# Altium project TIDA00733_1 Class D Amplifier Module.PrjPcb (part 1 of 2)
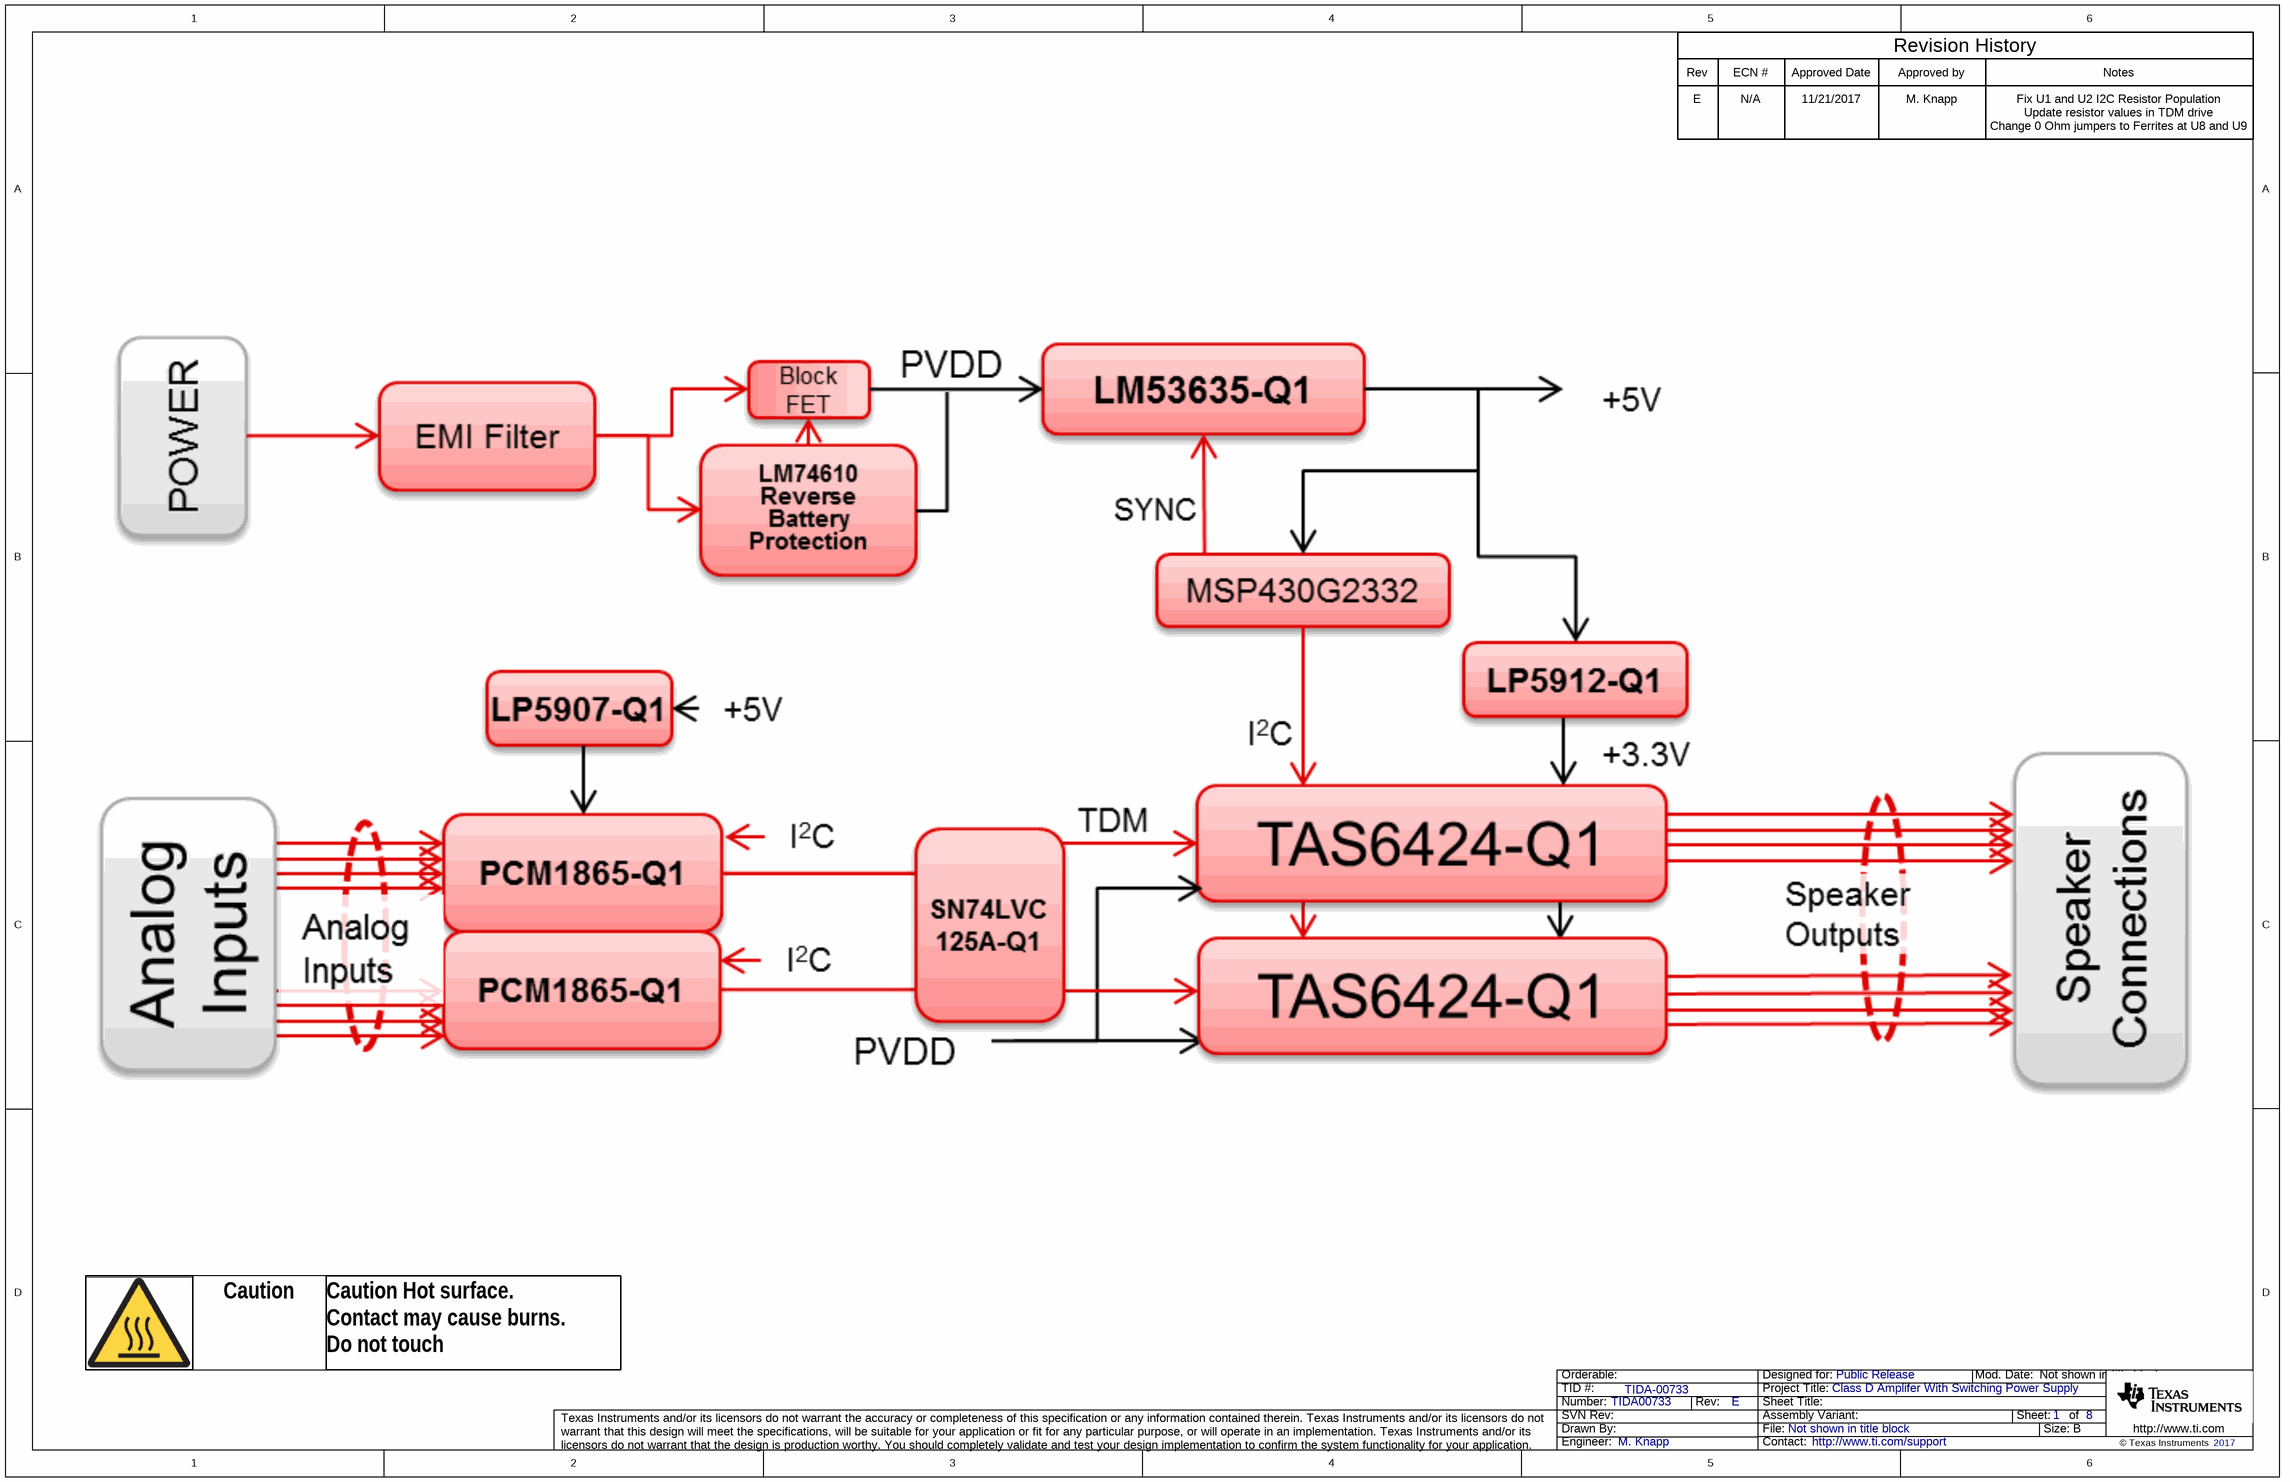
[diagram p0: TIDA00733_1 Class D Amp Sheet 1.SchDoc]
CopyrightYear: 2017; PCB_Layout: M. Knapp; PCB_Rev: E; PRJ_Customer: Public Release; PRJ_Engineer: M. Knapp; PRJ_Number: TIDA00733; PRJ_Title: Class D Amplifer With Switching Power Supply; SCH_Rev: E; TechSupport: http://www.ti.com/support; TID: TIDA-00733
8 sheets, 308 parts. Net scope: global (net labels, ports and power ports of the same name join across sheets).
Board file: TIDA00733_1 Class D Amp PCB.PcbDoc
Sheets:
  TIDA00733_1 Class D Amp Sheet 1.SchDoc
  TIDA00733_1 Class D Amp Sheet 2.SchDoc
  TIDA00733_1 Class D Amp Sheet 3.SchDoc
  TIDA00733_1 Class D Amp Sheet 4.SchDoc
  TIDA00733_1 Class D Amp Sheet 5.SchDoc
  TIDA00733_1 Class D Amp Sheet 6.SchDoc
  TIDA00733_1 Class D Amp Sheet 7.SchDoc
  TIDA00733_1 Class D Amp Sheet 8.SchDoc

## Sheet TIDA00733_1 Class D Amp Sheet 1.SchDoc
size 431 x 279 mm; Date: Not shown in title block; ApprovedBy: Not shown in title block; CheckedBy: Not shown in title block; Author: Not shown in title block; CompanyName: Not shown in title block; Engineer: Not shown in title block; Organization: Not shown in title block; Address1: Not shown in title block; Address2: Not shown in title block; Address3: Not shown in title block; Address4: Not shown in title block; DocumentNumber: 1; Revision: Use project parameter SCH_Rev; SheetNumber: 1; SheetTotal: 8; PageSetup: Record=PageOptions¦CenterHorizontal=True¦CenterVertical=True¦PrintScale=1.00¦XCorrection=1.00¦YCorrection=1.00¦PrintKind=0¦BorderSize=5000000¦LeftOffset=0¦BottomOffset=0¦Orientation=2¦PaperLength=1000¦PaperWidth=1000¦Scale=100¦PaperSource=15¦PrintQuality=600¦MediaType=1¦DitherType=10¦PaperKind=Letter¦PrintScaleMode=1

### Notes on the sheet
- Rev
- E
- ECN #
- N/A
- Approved Date
- 11/21/2017
- Approved by
- M. Knapp
- Revision History
- Notes
- Fix U1 and U2 I2C Resistor Population
- Update resistor values in TDM drive
- Change 0 Ohm jumpers to Ferrites at U8 and U9
- Caution
- Caution Hot surface.
  Contact may cause burns.
  Do not touch

## Sheet TIDA00733_1 Class D Amp Sheet 2.SchDoc
size 431 x 279 mm; Date: Not shown in title block; ApprovedBy: Not shown in title block; CheckedBy: Not shown in title block; Author: Not shown in title block; CompanyName: Not shown in title block; Engineer: Not shown in title block; Organization: Not shown in title block; Address1: Not shown in title block; Address2: Not shown in title block; Address3: Not shown in title block; Address4: Not shown in title block; DocumentNumber: 2; Revision: Use project parameter SCH_Rev; SheetNumber: 2; SheetTotal: 8; PageSetup: Record=PageOptions¦CenterHorizontal=True¦CenterVertical=True¦PrintScale=1.00¦XCorrection=1.00¦YCorrection=1.00¦PrintKind=0¦BorderSize=5000000¦LeftOffset=0¦BottomOffset=0¦Orientation=2¦PaperLength=1000¦PaperWidth=1000¦Scale=100¦PaperSource=15¦PrintQuality=600¦MediaType=1¦DitherType=10¦PaperKind=Letter¦PrintScaleMode=1
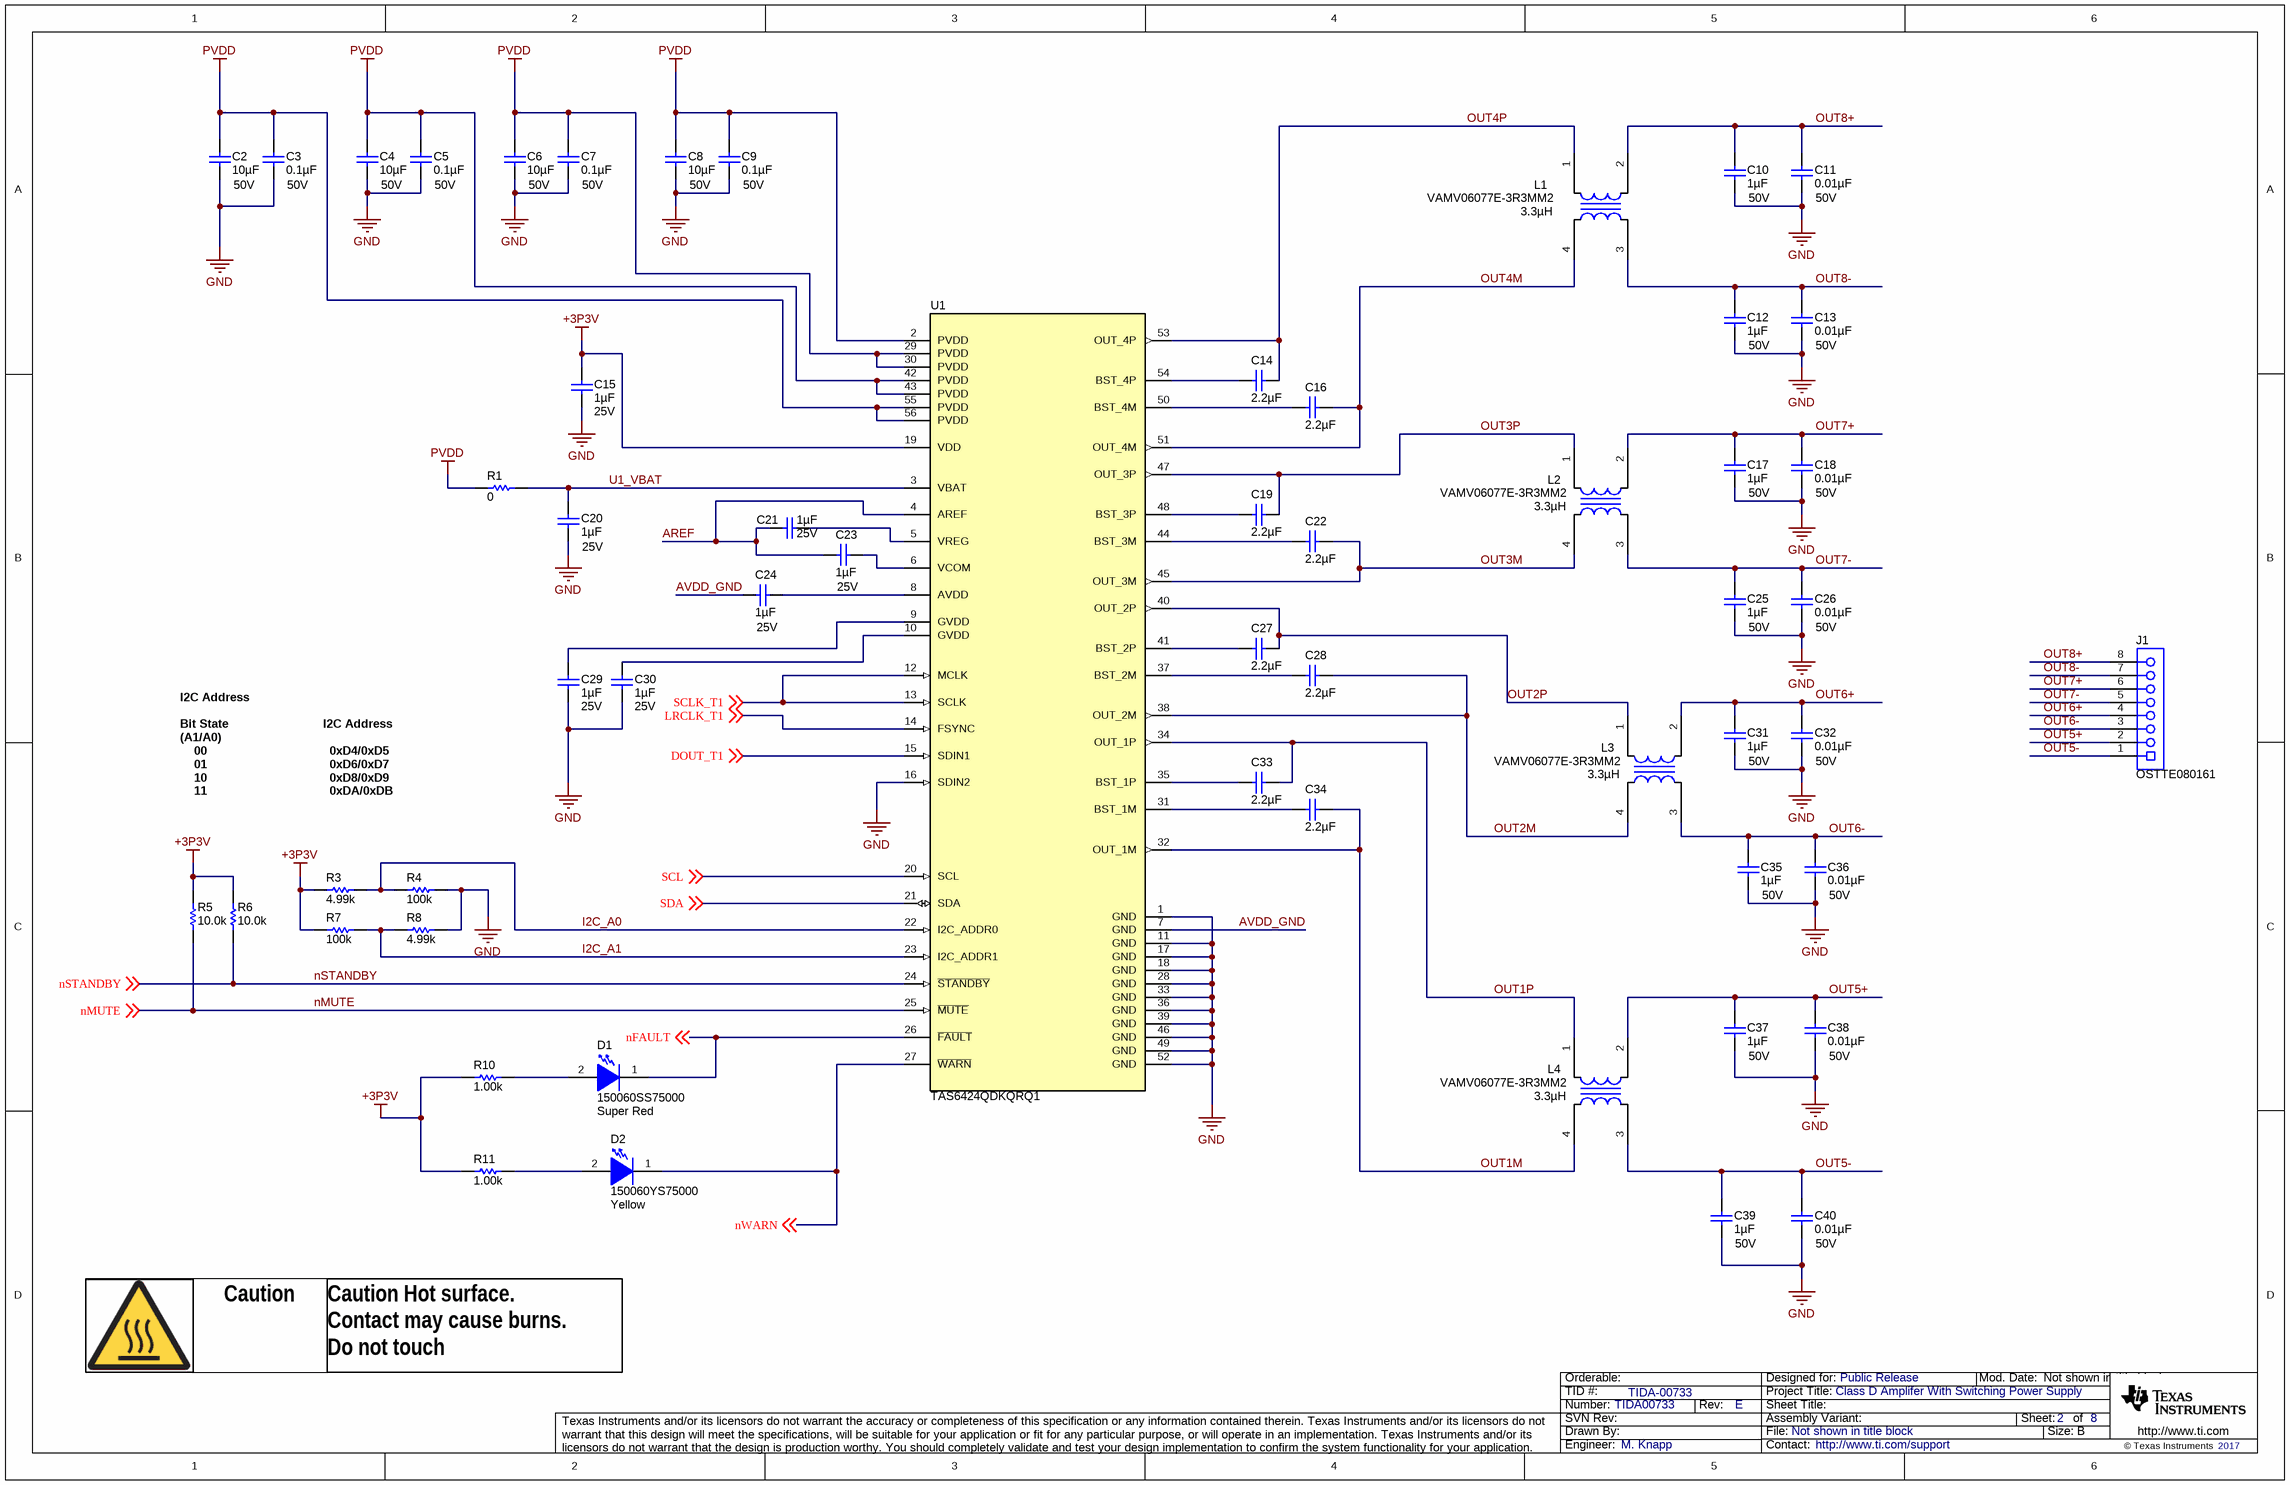
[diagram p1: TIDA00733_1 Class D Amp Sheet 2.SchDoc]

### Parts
C2  ValueDisplayed: 10µF  Value2: 50V  [1210_270]  (hidden comment: GRM32ER71H106KA12L)
C3  ValueDisplayed: 0.1µF  Value2: 50V  [0402L]  (hidden comment: C1005X7R1H104K050BB)
C4  ValueDisplayed: 10µF  Value2: 50V  [1210_270]  (hidden comment: GRM32ER71H106KA12L)
C5  ValueDisplayed: 0.1µF  Value2: 50V  [0402L]  (hidden comment: C1005X7R1H104K050BB)
C6  ValueDisplayed: 10µF  Value2: 50V  [1210_270]  (hidden comment: GRM32ER71H106KA12L)
C7  ValueDisplayed: 0.1µF  Value2: 50V  [0402L]  (hidden comment: C1005X7R1H104K050BB)
C8  ValueDisplayed: 10µF  Value2: 50V  [1210_270]  (hidden comment: GRM32ER71H106KA12L)
C9  ValueDisplayed: 0.1µF  Value2: 50V  [0402L]  (hidden comment: C1005X7R1H104K050BB)
C10  ValueDisplayed: 1µF  Value2: 50V  [0805L]  (hidden comment: GRM21BR71H105KA12L)
C11  ValueDisplayed: 0.01µF  Value2: 50V  [0402L]  (hidden comment: GCM155R71H103KA55D)
C12  ValueDisplayed: 1µF  Value2: 50V  [0805L]  (hidden comment: GRM21BR71H105KA12L)
C13  ValueDisplayed: 0.01µF  Value2: 50V  [0402L]  (hidden comment: GCM155R71H103KA55D)
C14  ValueDisplayed: 2.2µF  [0805L]  (hidden comment: C2012X7R1H225K125AC)
C15  ValueDisplayed: 1µF  Value2: 25V  [0603L]  (hidden comment: C1608X7R1E105K080AB)
C16  ValueDisplayed: 2.2µF  [0805L]  (hidden comment: C2012X7R1H225K125AC)
C17  ValueDisplayed: 1µF  Value2: 50V  [0805L]  (hidden comment: GRM21BR71H105KA12L)
C18  ValueDisplayed: 0.01µF  Value2: 50V  [0402L]  (hidden comment: GCM155R71H103KA55D)
C19  ValueDisplayed: 2.2µF  [0805L]  (hidden comment: C2012X7R1H225K125AC)
C20  ValueDisplayed: 1µF  Value2: 25V  [0603L]  (hidden comment: C1608X7R1E105K080AB)
C21  ValueDisplayed: 1µF  Value2: 25V  [0603L]  (hidden comment: C1608X7R1E105K080AB)
C22  ValueDisplayed: 2.2µF  [0805L]  (hidden comment: C2012X7R1H225K125AC)
C23  ValueDisplayed: 1µF  Value2: 25V  [0603L]  (hidden comment: C1608X7R1E105K080AB)
C24  ValueDisplayed: 1µF  Value2: 25V  [0603L]  (hidden comment: C1608X7R1E105K080AB)
C25  ValueDisplayed: 1µF  Value2: 50V  [0805L]  (hidden comment: GRM21BR71H105KA12L)
C26  ValueDisplayed: 0.01µF  Value2: 50V  [0402L]  (hidden comment: GCM155R71H103KA55D)
C27  ValueDisplayed: 2.2µF  [0805L]  (hidden comment: C2012X7R1H225K125AC)
C28  ValueDisplayed: 2.2µF  [0805L]  (hidden comment: C2012X7R1H225K125AC)
C29  ValueDisplayed: 1µF  Value2: 25V  [0603L]  (hidden comment: C1608X7R1E105K080AB)
C30  ValueDisplayed: 1µF  Value2: 25V  [0603L]  (hidden comment: C1608X7R1E105K080AB)
C31  ValueDisplayed: 1µF  Value2: 50V  [0805L]  (hidden comment: GRM21BR71H105KA12L)
C32  ValueDisplayed: 0.01µF  Value2: 50V  [0402L]  (hidden comment: GCM155R71H103KA55D)
C33  ValueDisplayed: 2.2µF  [0805L]  (hidden comment: C2012X7R1H225K125AC)
C34  ValueDisplayed: 2.2µF  [0805L]  (hidden comment: C2012X7R1H225K125AC)
C35  ValueDisplayed: 1µF  Value2: 50V  [0805L]  (hidden comment: GRM21BR71H105KA12L)
C36  ValueDisplayed: 0.01µF  Value2: 50V  [0402L]  (hidden comment: GCM155R71H103KA55D)
C37  ValueDisplayed: 1µF  Value2: 50V  [0805L]  (hidden comment: GRM21BR71H105KA12L)
C38  ValueDisplayed: 0.01µF  Value2: 50V  [0402L]  (hidden comment: GCM155R71H103KA55D)
C39  ValueDisplayed: 1µF  Value2: 50V  [0805L]  (hidden comment: GRM21BR71H105KA12L)
C40  ValueDisplayed: 0.01µF  Value2: 50V  [0402L]  (hidden comment: GCM155R71H103KA55D)
D1  value Super Red  [WL-SMCW_RED]  (hidden comment: 150060SS75000)
D2  value Yellow  [WL-SMCW_YELLOW]  (hidden comment: 150060YS75000)
J1  OSTTE080161  [On-Shore_OSTTE080161]
L1  VAMV06077E-3R3MM2  ValueDisplayed: 3.3µH  [Cyntec_VAMV06077E]
L2  VAMV06077E-3R3MM2  ValueDisplayed: 3.3µH  [Cyntec_VAMV06077E]
L3  VAMV06077E-3R3MM2  ValueDisplayed: 3.3µH  [Cyntec_VAMV06077E]
L4  VAMV06077E-3R3MM2  ValueDisplayed: 3.3µH  [Cyntec_VAMV06077E]
R1  ValueDisplayed: 0  [0805L]  (hidden comment: CRCW08050000Z0EA)
R3  ValueDisplayed: 4.99k  [0402L]  (hidden comment: CRCW04024K99FKED)
R4  ValueDisplayed: 100k  [0402L]  (hidden comment: CRCW0402100KFKED)
R5  ValueDisplayed: 10.0k  [0402L]  (hidden comment: CRCW040210K0FKED)
R6  ValueDisplayed: 10.0k  [0402L]  (hidden comment: CRCW040210K0FKED)
R7  ValueDisplayed: 100k  [0402L]  (hidden comment: CRCW0402100KFKED)
R8  ValueDisplayed: 4.99k  [0402L]  (hidden comment: CRCW04024K99FKED)
R10  ValueDisplayed: 1.00k  [0402L]  (hidden comment: CRCW04021K00FKED)
R11  ValueDisplayed: 1.00k  [0402L]  (hidden comment: CRCW04021K00FKED)
U1  TAS6424QDKQRQ1  [DKQ0056A]

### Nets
+3P3V: C15.1 R3.1 R5.2 R6.2 R7.1 R10.1 R11.1 U1.19(VDD)
GND: C2.2 C3.2 C4.2 C5.2 C6.2 C7.2 C8.2 C9.2 C10.2 C11.2 C12.2 C13.2 C15.2 C17.2 C18.2 C20.2 C25.2 C26.2 C29.2 C30.2 C31.2 C32.2 C35.2 C36.2 C37.2 C38.2 C39.2 C40.2 R4.2 R8.2 U1.1(GND) U1.11(GND) U1.16(SDIN2) U1.17(GND) U1.18(GND) U1.28(GND) U1.33(GND) U1.36(GND) U1.39(GND) U1.46(GND) U1.49(GND) U1.52(GND)
PVDD: C2.1 C3.1 C4.1 C5.1 C6.1 C7.1 C8.1 C9.1 R1.1 U1.2(PVDD) U1.29(PVDD) U1.30(PVDD) U1.42(PVDD) U1.43(PVDD) U1.55(PVDD) U1.56(PVDD)
AREF: C21.2 C23.2 U1.4(AREF)
AVDD_GND: C24.2 U1.7(GND)
DOUT_T1: U1.15(SDIN1) ; off-sheet DOUT_T1
I2C_A0: R3.2 R4.1 U1.22(I2C_ADDR0)
I2C_A1: R7.2 R8.1 U1.23(I2C_ADDR1)
LRCLK_T1: U1.14(FSYNC) ; off-sheet LRCLK_T1
nFAULT: D1.1(K) U1.26(~{FAULT}) ; off-sheet nFAULT
nMUTE: R5.1 U1.25(~{MUTE}) ; off-sheet nMUTE
nSTANDBY: R6.1 U1.24(~{STANDBY}) ; off-sheet nSTANDBY
nWARN: D2.1(K) U1.27(~{WARN}) ; off-sheet nWARN
OUT1M: C34.1 L4.4 U1.32(OUT_1M)
OUT1P: C33.1 L4.1 U1.34(OUT_1P)
OUT2M: C28.1 L3.4 U1.38(OUT_2M)
OUT2P: C27.1 L3.1 U1.40(OUT_2P)
OUT3M: C22.1 L2.4 U1.45(OUT_3M)
OUT3P: C19.1 L2.1 U1.47(OUT_3P)
OUT4M: C16.1 L1.4 U1.51(OUT_4M)
OUT4P: C14.1 L1.1 U1.53(OUT_4P)
OUT5+: C37.1 C38.1 J1.2 L4.2
OUT5-: C39.1 C40.1 J1.1 L4.3
OUT6+: C31.1 C32.1 J1.4 L3.2
OUT6-: C35.1 C36.1 J1.3 L3.3
OUT7+: C17.1 C18.1 J1.6 L2.2
OUT7-: C25.1 C26.1 J1.5 L2.3
OUT8+: C10.1 C11.1 J1.8 L1.2
OUT8-: C12.1 C13.1 J1.7 L1.3
SCL: U1.20(SCL) ; off-sheet SCL
SCLK_T1: U1.12(MCLK) U1.13(SCLK) ; off-sheet SCLK_T1
SDA: U1.21(SDA) ; off-sheet SDA
U1_VBAT: C20.1 R1.2 U1.3(VBAT)
NetC14_2: C14.2 U1.54(BST_4P)
NetC16_2: C16.2 U1.50(BST_4M)
NetC19_2: C19.2 U1.48(BST_3P)
NetC21_1: C21.1 U1.5(VREG)
NetC22_2: C22.2 U1.44(BST_3M)
NetC23_1: C23.1 U1.6(VCOM)
NetC24_1: C24.1 U1.8(AVDD)
NetC27_2: C27.2 U1.41(BST_2P)
NetC28_2: C28.2 U1.37(BST_2M)
NetC29_1: C29.1 U1.9(GVDD)
NetC30_1: C30.1 U1.10(GVDD)
NetC33_2: C33.2 U1.35(BST_1P)
NetC34_2: C34.2 U1.31(BST_1M)
NetD1_2: D1.2(A) R10.2
NetD2_2: D2.2(A) R11.2

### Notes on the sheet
- I2C Address
  Bit State                           I2C Address
  (A1/A0)
  00                                   0xD4/0xD5
  01                                   0xD6/0xD7
  10                                   0xD8/0xD9
  11                                   0xDA/0xDB
- Caution
- Caution Hot surface.
  Contact may cause burns.
  Do not touch

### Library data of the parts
C2 C4 C6 C8 = GRM32ER71H106KA12L: CAP, CERM, 10 µF, 50 V, +/- 10%, X7R, 1210; Manufacturer: MuRata; Polarized: N; CompType: Capacitor; Value: 10uF; U/M: EA; Cap_F: 0.00001; Tolerance_%: 10; Value1: Unknown; VDC_V: 50; TaMin_C: -55; TaMax_C: 125; Cap_Case: 1210; AEC Category: Q200; SizeArea_mm2: 8; SizeAreaWB_mm2: 14.7; SizeX_mm: 3.2; SizeY_mm: 2.5; SizeZ_mm: 2.7
C3 C5 C7 C9 = C1005X7R1H104K050BB: CAP, CERM, 0.1 µF, 50 V, +/- 10%, X7R, 0402; Manufacturer: TDK; Polarized: N; CompType: Capacitor; Value: 0.1uF; U/M: EA; Cap_F: 0.0000001; Tolerance_%: 10; ESR_ohm: 0.039064; Value1: 0.039064 ohm; VDC_V: 50; IRMS_A: 0.814669; TaMin_C: -55; TaMax_C: 125; Cap_Case: 0402; AEC Category: Q200; SizeArea_mm2: 0.5; SizeAreaWB_mm2: 3; SizeX_mm: 1; SizeZ_mm: 0.6
C10 C12 C17 C25 C31 C35 C37 C39 = GRM21BR71H105KA12L: CAP, CERM, 1 µF, 50 V, +/- 10%, X7R, 0805; Manufacturer: MuRata; Polarized: N; CompType: Capacitor; Value: 1uF; U/M: EA; Cap_F: 0.000001; Tolerance_%: 10; Value1: Unknown; VDC_V: 50; TaMin_C: -55; TaMax_C: 125; Cap_Case: 0805; AEC Category: Q200; SizeArea_mm2: 2.5; SizeAreaWB_mm2: 6.75; SizeX_mm: 2; SizeY_mm: 1.25; SizeZ_mm: 1.45
C11 C13 C18 C26 C32 C36 C38 C40 = GCM155R71H103KA55D: CAP, CERM, 0.01 µF, 50 V, +/- 10%, C0G/NP0, 0402; Manufacturer: MuRata; Polarized: N; CompType: Capacitor; Value: 0.01uF; U/M: EA; Cap_F: 0.00000001; Tolerance_%: 10; Value1: Unknown; VDC_V: 50; TaMin_C: -55; TaMax_C: 125; Cap_Case: 0402; AEC Category: Q200; SizeArea_mm2: 0.5; SizeAreaWB_mm2: 3; SizeX_mm: 1; SizeZ_mm: 0.6
C14 C16 C19 C22 C27 C28 C33 C34 = C2012X7R1H225K125AC: CAP, CERM, 2.2 µF, 50 V, +/- 10%, X7R, 0805; Manufacturer: TDK; Polarized: N; CompType: Capacitor; Value: 2.2uF; U/M: EA; Cap_F: 0.0000022; Tolerance_%: 10; ESR_ohm: 0.00366; Value1: 0.00366 ohm; VDC_V: 50; Value2: 50V; IRMS_A: 3.41207; TaMin_C: -55; TaMax_C: 125; Cap_Case: 0805; AEC Category: Q200; SizeArea_mm2: 2.5; SizeAreaWB_mm2: 6.75; SizeX_mm: 2; SizeY_mm: 1.25; SizeZ_mm: 1.45
C15 C20 C21 C23 C24 C29 C30 = C1608X7R1E105K080AB: CAP, CERM, 1 µF, 25 V, +/- 10%, X7R, 0603; Manufacturer: TDK; Polarized: N; CompType: Capacitor; Value: 1uF; U/M: EA; Cap_F: 0.000001; Tolerance_%: 10; Value1: Unknown; VDC_V: 25; TaMin_C: -55; TaMax_C: 125; Cap_Case: 0603; AEC Category: Q200; SizeArea_mm2: 1.28; SizeAreaWB_mm2: 4.68; SizeX_mm: 1.6; SizeY_mm: 0.8; SizeZ_mm: 1
D1 = 150060SS75000: LED, Super Red, SMD; Manufacturer: Wurth Elektronik; Type: AlInGaP; Vf_V: 1.9; Value2: 1.9V; Io_A: 0.02; Value1: W; U/M: EA
D2 = 150060YS75000: LED, Yellow, SMD; Manufacturer: Wurth Elektronik; Type: AlInGaP; Vf_V: 2; Value2: 2V; Io_A: 0.02; Value1: W; U/M: EA
J1 = OSTTE080161: Terminal Block, 8x1, 3.5mm, TH; Manufacturer: On-Shore Technology; SymbolCreator: a0411947
L1-L4 = VAMV06077E-3R3MM2: Coupled inductor, 3.3 µH, 11.1 A, 0.0192 ohm, SMD; Manufacturer: Cyntec; SymbolCreator: Altium; Value: 3.3uH; Ind_H: 3.3E-6; DCR_ohm: 0.0192
R1 = CRCW08050000Z0EA: RES, 0, 5%, 0.125 W, 0805; Manufacturer: Vishay-Dale; CompType: Resistor; Value: 0; Value_Code: 0000; Tolerance_%: 5; Power_W: 0.125; Value2: 0.125W; VDC_V: 150; TempCo: 200 ppm/C; EIA_Code: E24; U/M: EA; AEC Category: Q200; SizeArea_mm2: 2.5; SizeX_mm: 2; SizeY_mm: 1.25; SizeZ_mm: 1.45
R3 = CRCW04024K99FKED: RES, 4.99 k, 1%, 0.063 W, 0402; Manufacturer: Vishay-Dale; CompType: Resistor; Value: 4.99k; Res_ohm: 4990; Value_Code: 4k99; Tolerance_%: 1; Power_W: 0.063; Value2: 0.063W; VDC_V: 50; TempCo: 100 ppm/C; EIA_Code: E96; U/M: EA; AEC Category: Q200; SizeArea_mm2: 0.5; SizeZ_mm: 0.6; Green_Lifecycle: Active; Green_REACh: Passed
R4 = CRCW0402100KFKED: RES, 100 k, 1%, 0.063 W, 0402; Manufacturer: Vishay-Dale; CompType: Resistor; Value: 100k; Res_ohm: 100000; Tolerance_%: 1; Power_W: 0.063; Value2: 0.063W; VDC_V: 50; TempCo: 100 ppm/C; EIA_Code: E96; U/M: EA; AEC Category: Q200; SizeArea_mm2: 0.5; SizeZ_mm: 0.6; Green_Lifecycle: Active; Green_REACh: Passed
R5 R6 = CRCW040210K0FKED: RES, 10.0 k, 1%, 0.063 W, 0402; Manufacturer: Vishay-Dale; CompType: Resistor; Value: 10.0k; Res_ohm: 10000; Value_Code: 10k0; Tolerance_%: 1; Power_W: 0.063; Value2: 0.063W; VDC_V: 50; TempCo: 100 ppm/C; EIA_Code: E96; U/M: EA; AEC Category: Q200; SizeArea_mm2: 0.5; SizeZ_mm: 0.6
R7 = CRCW0402100KFKED: RES, 100 k, 1%, 0.063 W, 0402; Manufacturer: Vishay-Dale; CompType: Resistor; Value: 100k; Res_ohm: 100000; Tolerance_%: 1; Power_W: 0.063; Value2: 0.063W; VDC_V: 50; TempCo: 100 ppm/C; EIA_Code: E96; U/M: EA; AEC Category: Q200; SizeArea_mm2: 0.5; SizeZ_mm: 0.6
R8 = CRCW04024K99FKED: RES, 4.99 k, 1%, 0.063 W, 0402; Manufacturer: Vishay-Dale; CompType: Resistor; Value: 4.99k; Res_ohm: 4990; Value_Code: 4k99; Tolerance_%: 1; Power_W: 0.063; Value2: 0.063W; VDC_V: 50; TempCo: 100 ppm/C; EIA_Code: E96; U/M: EA; AEC Category: Q200; SizeArea_mm2: 0.5; SizeZ_mm: 0.6
R10 R11 = CRCW04021K00FKED: RES, 1.00 k, 1%, 0.063 W, 0402; Manufacturer: Vishay-Dale; CompType: Resistor; Value: 1.00k; Res_ohm: 1000; Value_Code: 1k00; Tolerance_%: 1; Power_W: 0.063; Value2: 0.063W; VDC_V: 50; TempCo: 100 ppm/C; EIA_Code: E96; U/M: EA; AEC Category: Q200; SizeArea_mm2: 0.5; SizeZ_mm: 0.6
U1 = TAS6424QDKQRQ1: Four-Channel Digital Input Automotive Digital Amplifier, DKQ0056A; Manufacturer: Texas Instruments; SymbolCreator: Altium; CompType: IC; U/M: EA; SizeArea_mm2: 190.5435; SizeAreaWB_mm2: 252.0635; SizeX_mm: 10.35; SizeY_mm: 18.41; SizeZ_mm: 2.79

## Sheet TIDA00733_1 Class D Amp Sheet 3.SchDoc
size 431 x 279 mm; Date: Not shown in title block; ApprovedBy: Not shown in title block; CheckedBy: Not shown in title block; Author: Not shown in title block; CompanyName: Not shown in title block; Engineer: Not shown in title block; Organization: Not shown in title block; Address1: Not shown in title block; Address2: Not shown in title block; Address3: Not shown in title block; Address4: Not shown in title block; DocumentNumber: 3; Revision: Use project parameter SCH_Rev; SheetNumber: 3; SheetTotal: 8; PageSetup: Record=PageOptions¦CenterHorizontal=True¦CenterVertical=True¦PrintScale=1.00¦XCorrection=1.00¦YCorrection=1.00¦PrintKind=0¦BorderSize=5000000¦LeftOffset=0¦BottomOffset=0¦Orientation=2¦PaperLength=1000¦PaperWidth=1000¦Scale=100¦PaperSource=15¦PrintQuality=600¦MediaType=1¦DitherType=10¦PaperKind=Letter¦PrintScaleMode=1
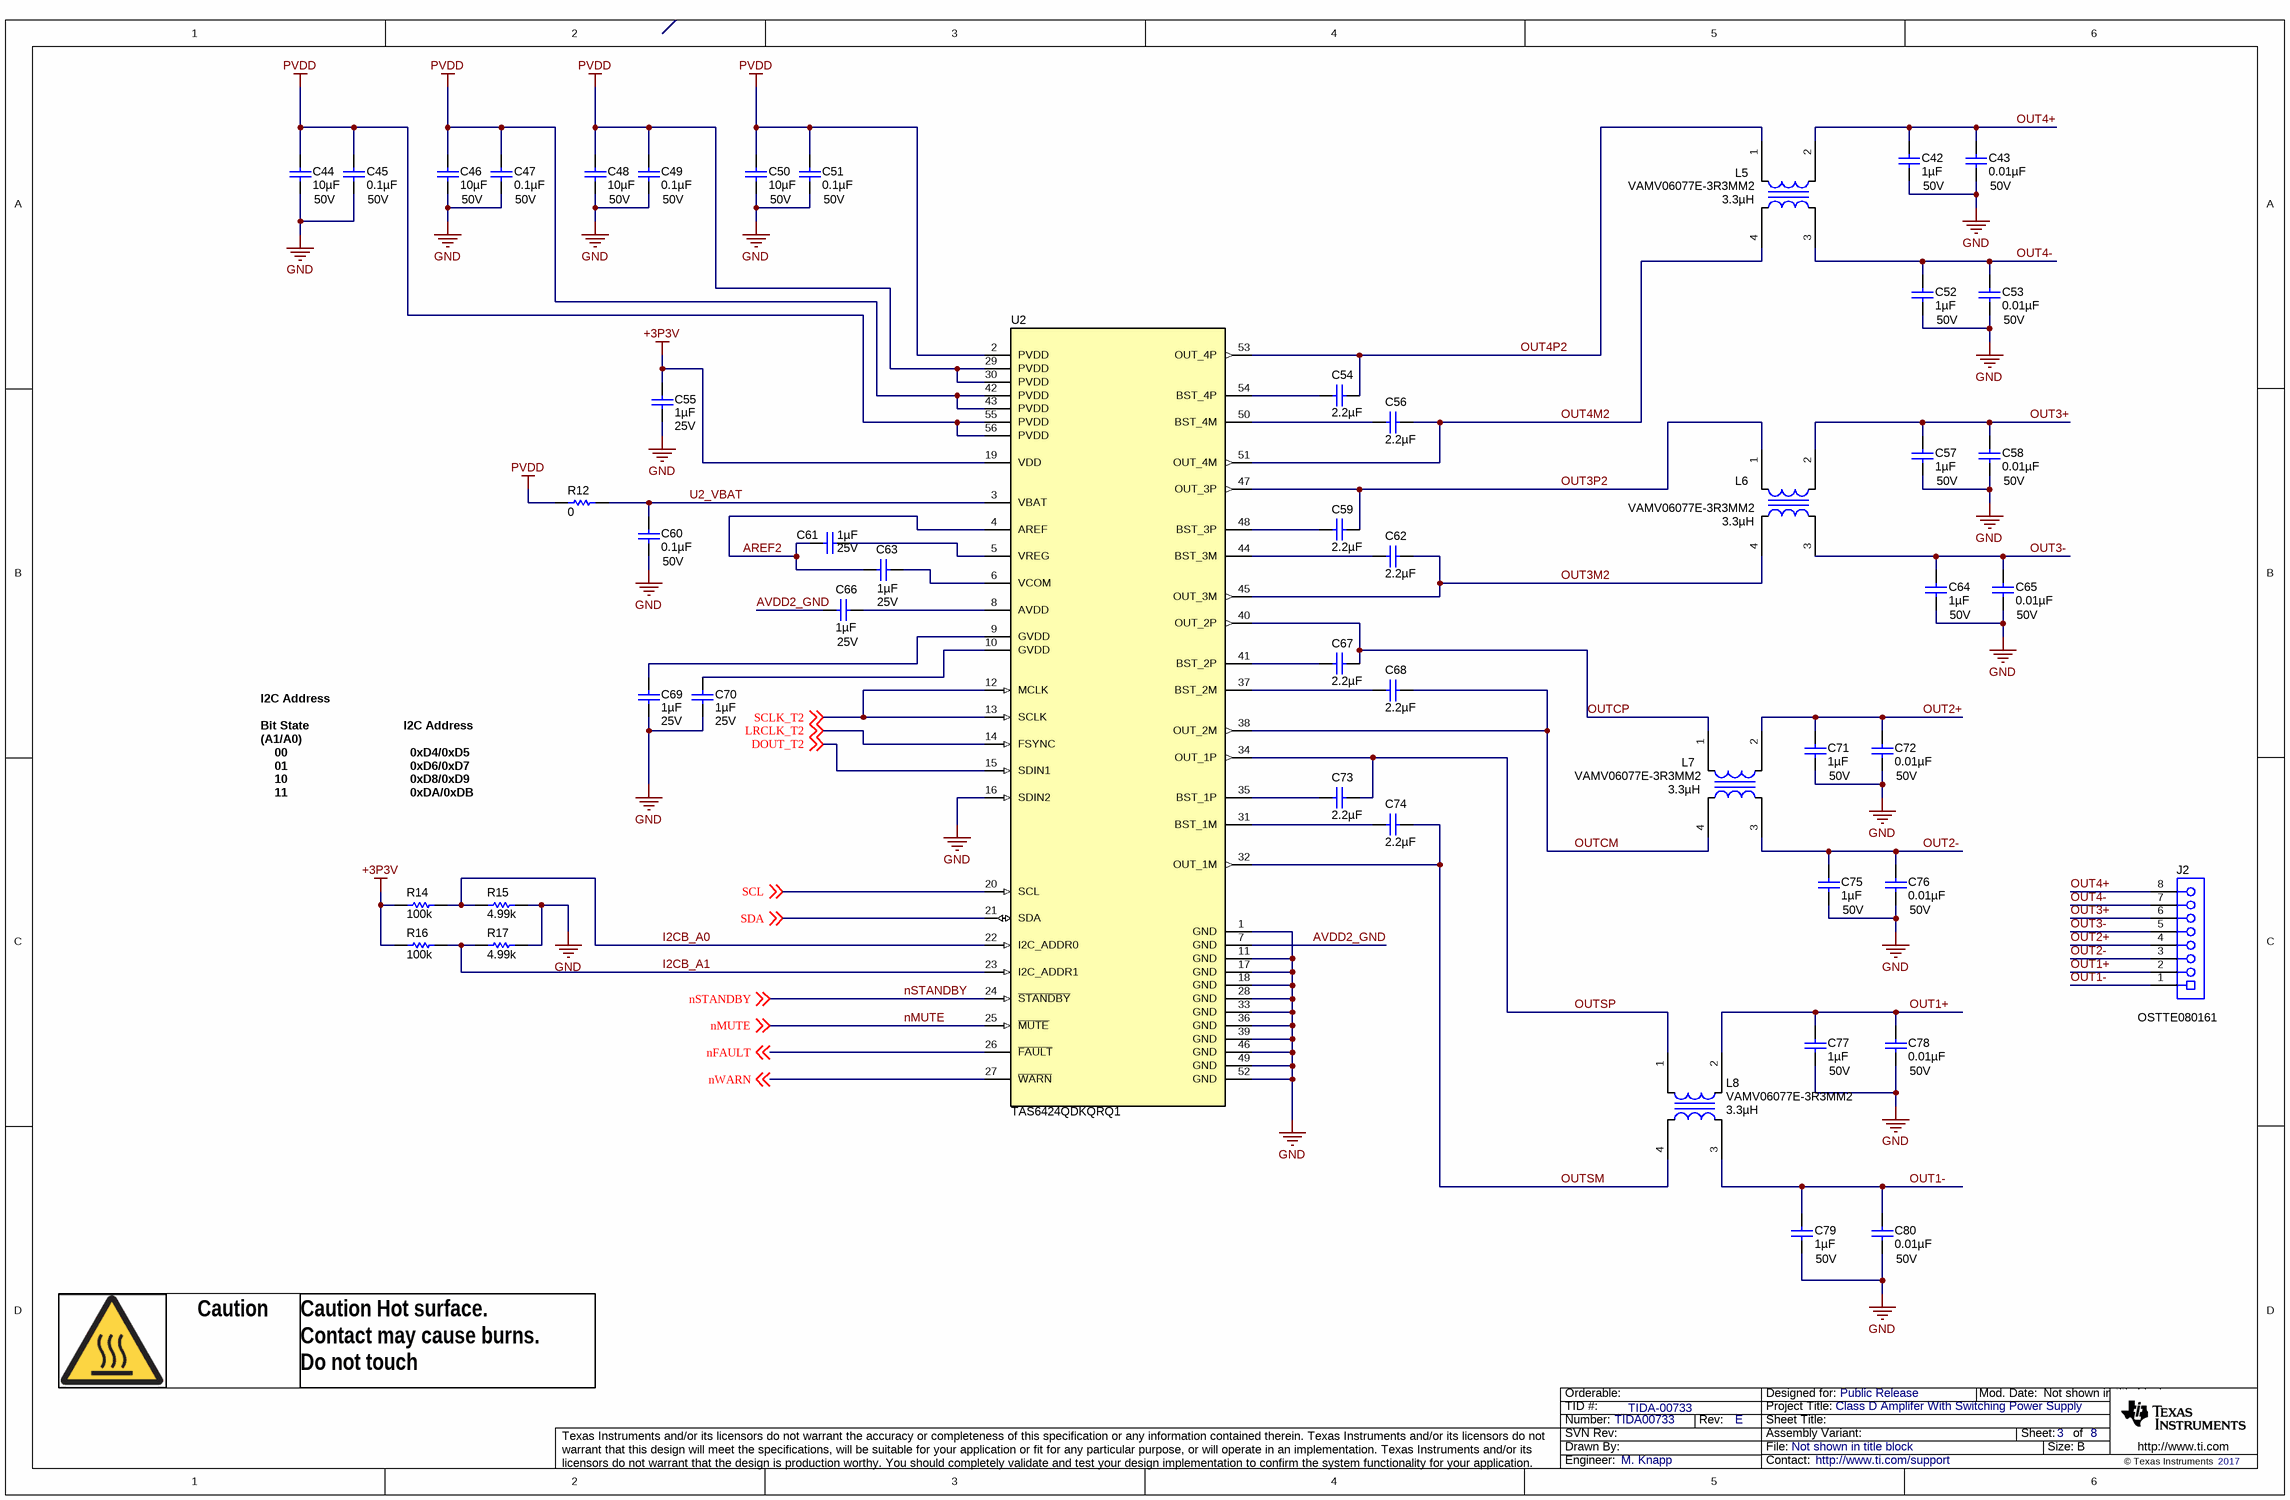
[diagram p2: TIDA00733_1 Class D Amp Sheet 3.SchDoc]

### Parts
C42  ValueDisplayed: 1µF  Value2: 50V  [0805L]  (hidden comment: GRM21BR71H105KA12L)
C43  ValueDisplayed: 0.01µF  Value2: 50V  [0402L]  (hidden comment: GCM155R71H103KA55D)
C44  ValueDisplayed: 10µF  Value2: 50V  [1210_270]  (hidden comment: GRM32ER71H106KA12L)
C45  ValueDisplayed: 0.1µF  Value2: 50V  [0402L]  (hidden comment: C1005X7R1H104K050BB)
C46  ValueDisplayed: 10µF  Value2: 50V  [1210_270]  (hidden comment: GRM32ER71H106KA12L)
C47  ValueDisplayed: 0.1µF  Value2: 50V  [0402L]  (hidden comment: C1005X7R1H104K050BB)
C48  ValueDisplayed: 10µF  Value2: 50V  [1210_270]  (hidden comment: GRM32ER71H106KA12L)
C49  ValueDisplayed: 0.1µF  Value2: 50V  [0402L]  (hidden comment: C1005X7R1H104K050BB)
C50  ValueDisplayed: 10µF  Value2: 50V  [1210_270]  (hidden comment: GRM32ER71H106KA12L)
C51  ValueDisplayed: 0.1µF  Value2: 50V  [0402L]  (hidden comment: C1005X7R1H104K050BB)
C52  ValueDisplayed: 1µF  Value2: 50V  [0805L]  (hidden comment: GRM21BR71H105KA12L)
C53  ValueDisplayed: 0.01µF  Value2: 50V  [0402L]  (hidden comment: GCM155R71H103KA55D)
C54  ValueDisplayed: 2.2µF  [0805L]  (hidden comment: C2012X7R1H225K125AC)
C55  ValueDisplayed: 1µF  Value2: 25V  [0603L]  (hidden comment: C1608X7R1E105K080AB)
C56  ValueDisplayed: 2.2µF  [0805L]  (hidden comment: C2012X7R1H225K125AC)
C57  ValueDisplayed: 1µF  Value2: 50V  [0805L]  (hidden comment: GRM21BR71H105KA12L)
C58  ValueDisplayed: 0.01µF  Value2: 50V  [0402L]  (hidden comment: GCM155R71H103KA55D)
C59  ValueDisplayed: 2.2µF  [0805L]  (hidden comment: C2012X7R1H225K125AC)
C60  ValueDisplayed: 0.1µF  Value2: 50V  [0402L]  (hidden comment: C1005X7R1H104K050BB)
C61  ValueDisplayed: 1µF  Value2: 25V  [0603L]  (hidden comment: C1608X7R1E105K080AB)
C62  ValueDisplayed: 2.2µF  [0805L]  (hidden comment: C2012X7R1H225K125AC)
C63  ValueDisplayed: 1µF  Value2: 25V  [0603L]  (hidden comment: C1608X7R1E105K080AB)
C64  ValueDisplayed: 1µF  Value2: 50V  [0805L]  (hidden comment: GRM21BR71H105KA12L)
C65  ValueDisplayed: 0.01µF  Value2: 50V  [0402L]  (hidden comment: GCM155R71H103KA55D)
C66  ValueDisplayed: 1µF  Value2: 25V  [0603L]  (hidden comment: C1608X7R1E105K080AB)
C67  ValueDisplayed: 2.2µF  [0805L]  (hidden comment: C2012X7R1H225K125AC)
C68  ValueDisplayed: 2.2µF  [0805L]  (hidden comment: C2012X7R1H225K125AC)
C69  ValueDisplayed: 1µF  Value2: 25V  [0603L]  (hidden comment: C1608X7R1E105K080AB)
C70  ValueDisplayed: 1µF  Value2: 25V  [0603L]  (hidden comment: C1608X7R1E105K080AB)
C71  ValueDisplayed: 1µF  Value2: 50V  [0805L]  (hidden comment: GRM21BR71H105KA12L)
C72  ValueDisplayed: 0.01µF  Value2: 50V  [0402L]  (hidden comment: GCM155R71H103KA55D)
C73  ValueDisplayed: 2.2µF  [0805L]  (hidden comment: C2012X7R1H225K125AC)
C74  ValueDisplayed: 2.2µF  [0805L]  (hidden comment: C2012X7R1H225K125AC)
C75  ValueDisplayed: 1µF  Value2: 50V  [0805L]  (hidden comment: GRM21BR71H105KA12L)
C76  ValueDisplayed: 0.01µF  Value2: 50V  [0402L]  (hidden comment: GCM155R71H103KA55D)
C77  ValueDisplayed: 1µF  Value2: 50V  [0805L]  (hidden comment: GRM21BR71H105KA12L)
C78  ValueDisplayed: 0.01µF  Value2: 50V  [0402L]  (hidden comment: GCM155R71H103KA55D)
C79  ValueDisplayed: 1µF  Value2: 50V  [0805L]  (hidden comment: GRM21BR71H105KA12L)
C80  ValueDisplayed: 0.01µF  Value2: 50V  [0402L]  (hidden comment: GCM155R71H103KA55D)
J2  OSTTE080161  [On-Shore_OSTTE080161]
L5  VAMV06077E-3R3MM2  ValueDisplayed: 3.3µH  [Cyntec_VAMV06077E]
L6  VAMV06077E-3R3MM2  ValueDisplayed: 3.3µH  [Cyntec_VAMV06077E]
L7  VAMV06077E-3R3MM2  ValueDisplayed: 3.3µH  [Cyntec_VAMV06077E]
L8  VAMV06077E-3R3MM2  ValueDisplayed: 3.3µH  [Cyntec_VAMV06077E]
R12  ValueDisplayed: 0  [0805L]  (hidden comment: CRCW08050000Z0EA)
R14  ValueDisplayed: 100k  [0402L]  (hidden comment: CRCW0402100KFKED)
R15  ValueDisplayed: 4.99k  [0402L]  (hidden comment: CRCW04024K99FKED)
R16  ValueDisplayed: 100k  [0402L]  (hidden comment: CRCW0402100KFKED)
R17  ValueDisplayed: 4.99k  [0402L]  (hidden comment: CRCW04024K99FKED)
U2  TAS6424QDKQRQ1  [DKQ0056A]

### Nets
+3P3V: C55.1 R14.1 R16.1 U2.19(VDD)
GND: C42.2 C43.2 C44.2 C45.2 C46.2 C47.2 C48.2 C49.2 C50.2 C51.2 C52.2 C53.2 C55.2 C57.2 C58.2 C60.2 C64.2 C65.2 C69.2 C70.2 C71.2 C72.2 C75.2 C76.2 C77.2 C78.2 C79.2 C80.2 R15.2 R17.2 U2.1(GND) U2.11(GND) U2.16(SDIN2) U2.17(GND) U2.18(GND) U2.28(GND) U2.33(GND) U2.36(GND) U2.39(GND) U2.46(GND) U2.49(GND) U2.52(GND)
PVDD: C44.1 C45.1 C46.1 C47.1 C48.1 C49.1 C50.1 C51.1 R12.1 U2.2(PVDD) U2.29(PVDD) U2.30(PVDD) U2.42(PVDD) U2.43(PVDD) U2.55(PVDD) U2.56(PVDD)
AREF2: C61.2 C63.2 U2.4(AREF)
AVDD2_GND: C66.2 U2.7(GND)
DOUT_T2: U2.15(SDIN1) ; off-sheet DOUT_T2
I2CB_A0: R14.2 R15.1 U2.22(I2C_ADDR0)
I2CB_A1: R16.2 R17.1 U2.23(I2C_ADDR1)
LRCLK_T2: U2.14(FSYNC) ; off-sheet LRCLK_T2
nFAULT: U2.26(~{FAULT}) ; off-sheet nFAULT
nMUTE: U2.25(~{MUTE}) ; off-sheet nMUTE
nSTANDBY: U2.24(~{STANDBY}) ; off-sheet nSTANDBY
nWARN: U2.27(~{WARN}) ; off-sheet nWARN
OUT1+: C77.1 C78.1 J2.2 L8.2
OUT1-: C79.1 C80.1 J2.1 L8.3
OUT2+: C71.1 C72.1 J2.4 L7.2
OUT2-: C75.1 C76.1 J2.3 L7.3
OUT3+: C57.1 C58.1 J2.6 L6.2
OUT3-: C64.1 C65.1 J2.5 L6.3
OUT3M2: C62.1 L6.4 U2.45(OUT_3M)
OUT3P2: C59.1 L6.1 U2.47(OUT_3P)
OUT4+: C42.1 C43.1 J2.8 L5.2
OUT4-: C52.1 C53.1 J2.7 L5.3
OUT4M2: C56.1 L5.4 U2.51(OUT_4M)
OUT4P2: C54.1 L5.1 U2.53(OUT_4P)
OUTCM: C68.1 L7.4 U2.38(OUT_2M)
OUTCP: C67.1 L7.1 U2.40(OUT_2P)
OUTSM: C74.1 L8.4 U2.32(OUT_1M)
OUTSP: C73.1 L8.1 U2.34(OUT_1P)
SCL: U2.20(SCL) ; off-sheet SCL
SCLK_T2: U2.12(MCLK) U2.13(SCLK) ; off-sheet SCLK_T2
SDA: U2.21(SDA) ; off-sheet SDA
U2_VBAT: C60.1 R12.2 U2.3(VBAT)
NetC54_2: C54.2 U2.54(BST_4P)
NetC56_2: C56.2 U2.50(BST_4M)
NetC59_2: C59.2 U2.48(BST_3P)
NetC61_1: C61.1 U2.5(VREG)
NetC62_2: C62.2 U2.44(BST_3M)
NetC63_1: C63.1 U2.6(VCOM)
NetC66_1: C66.1 U2.8(AVDD)
NetC67_2: C67.2 U2.41(BST_2P)
NetC68_2: C68.2 U2.37(BST_2M)
NetC69_1: C69.1 U2.9(GVDD)
NetC70_1: C70.1 U2.10(GVDD)
NetC73_2: C73.2 U2.35(BST_1P)
NetC74_2: C74.2 U2.31(BST_1M)

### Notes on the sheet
- I2C Address
  Bit State                           I2C Address
  (A1/A0)
  00                                   0xD4/0xD5
  01                                   0xD6/0xD7
  10                                   0xD8/0xD9
  11                                   0xDA/0xDB
- Caution
- Caution Hot surface.
  Contact may cause burns.
  Do not touch

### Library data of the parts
C42 C52 C57 C64 C71 C75 C77 C79 = GRM21BR71H105KA12L: as C10 on sheet TIDA00733_1 Class D Amp Sheet 2
C43 C53 C58 C65 C72 C76 C78 C80 = GCM155R71H103KA55D: as C11 on sheet TIDA00733_1 Class D Amp Sheet 2
C44 C46 C48 C50 = GRM32ER71H106KA12L: as C2 on sheet TIDA00733_1 Class D Amp Sheet 2
C45 C47 C49 C51 C60 = C1005X7R1H104K050BB: as C3 on sheet TIDA00733_1 Class D Amp Sheet 2
C54 C56 C59 C62 C67 C68 C73 C74 = C2012X7R1H225K125AC: as C14 on sheet TIDA00733_1 Class D Amp Sheet 2
C55 C61 C63 C66 C69 C70 = C1608X7R1E105K080AB: as C15 on sheet TIDA00733_1 Class D Amp Sheet 2
J2 = OSTTE080161: as J1 on sheet TIDA00733_1 Class D Amp Sheet 2
L5-L8 = VAMV06077E-3R3MM2: as L1 on sheet TIDA00733_1 Class D Amp Sheet 2
R12 = CRCW08050000Z0EA: as R1 on sheet TIDA00733_1 Class D Amp Sheet 2
R14 = CRCW0402100KFKED: as R4 on sheet TIDA00733_1 Class D Amp Sheet 2
R15 = CRCW04024K99FKED: as R3 on sheet TIDA00733_1 Class D Amp Sheet 2
R16 = CRCW0402100KFKED: as R7 on sheet TIDA00733_1 Class D Amp Sheet 2
R17 = CRCW04024K99FKED: as R8 on sheet TIDA00733_1 Class D Amp Sheet 2
U2 = TAS6424QDKQRQ1: as U1 on sheet TIDA00733_1 Class D Amp Sheet 2

## Sheet TIDA00733_1 Class D Amp Sheet 4.SchDoc
size 431 x 279 mm; Date: Not shown in title block; ApprovedBy: Not shown in title block; CheckedBy: Not shown in title block; Author: Not shown in title block; CompanyName: Not shown in title block; Engineer: Not shown in title block; Organization: Not shown in title block; Address1: Not shown in title block; Address2: Not shown in title block; Address3: Not shown in title block; Address4: Not shown in title block; DocumentNumber: 4; Revision: Use project parameter SCH_Rev; SheetNumber: 4; SheetTotal: 8; PageSetup: Record=PageOptions¦CenterHorizontal=True¦CenterVertical=True¦PrintScale=1.00¦XCorrection=1.00¦YCorrection=1.00¦PrintKind=0¦BorderSize=5000000¦LeftOffset=0¦BottomOffset=0¦Orientation=2¦PaperLength=1000¦PaperWidth=1000¦Scale=100¦PaperSource=15¦PrintQuality=600¦MediaType=1¦DitherType=10¦PaperKind=Letter¦PrintScaleMode=1
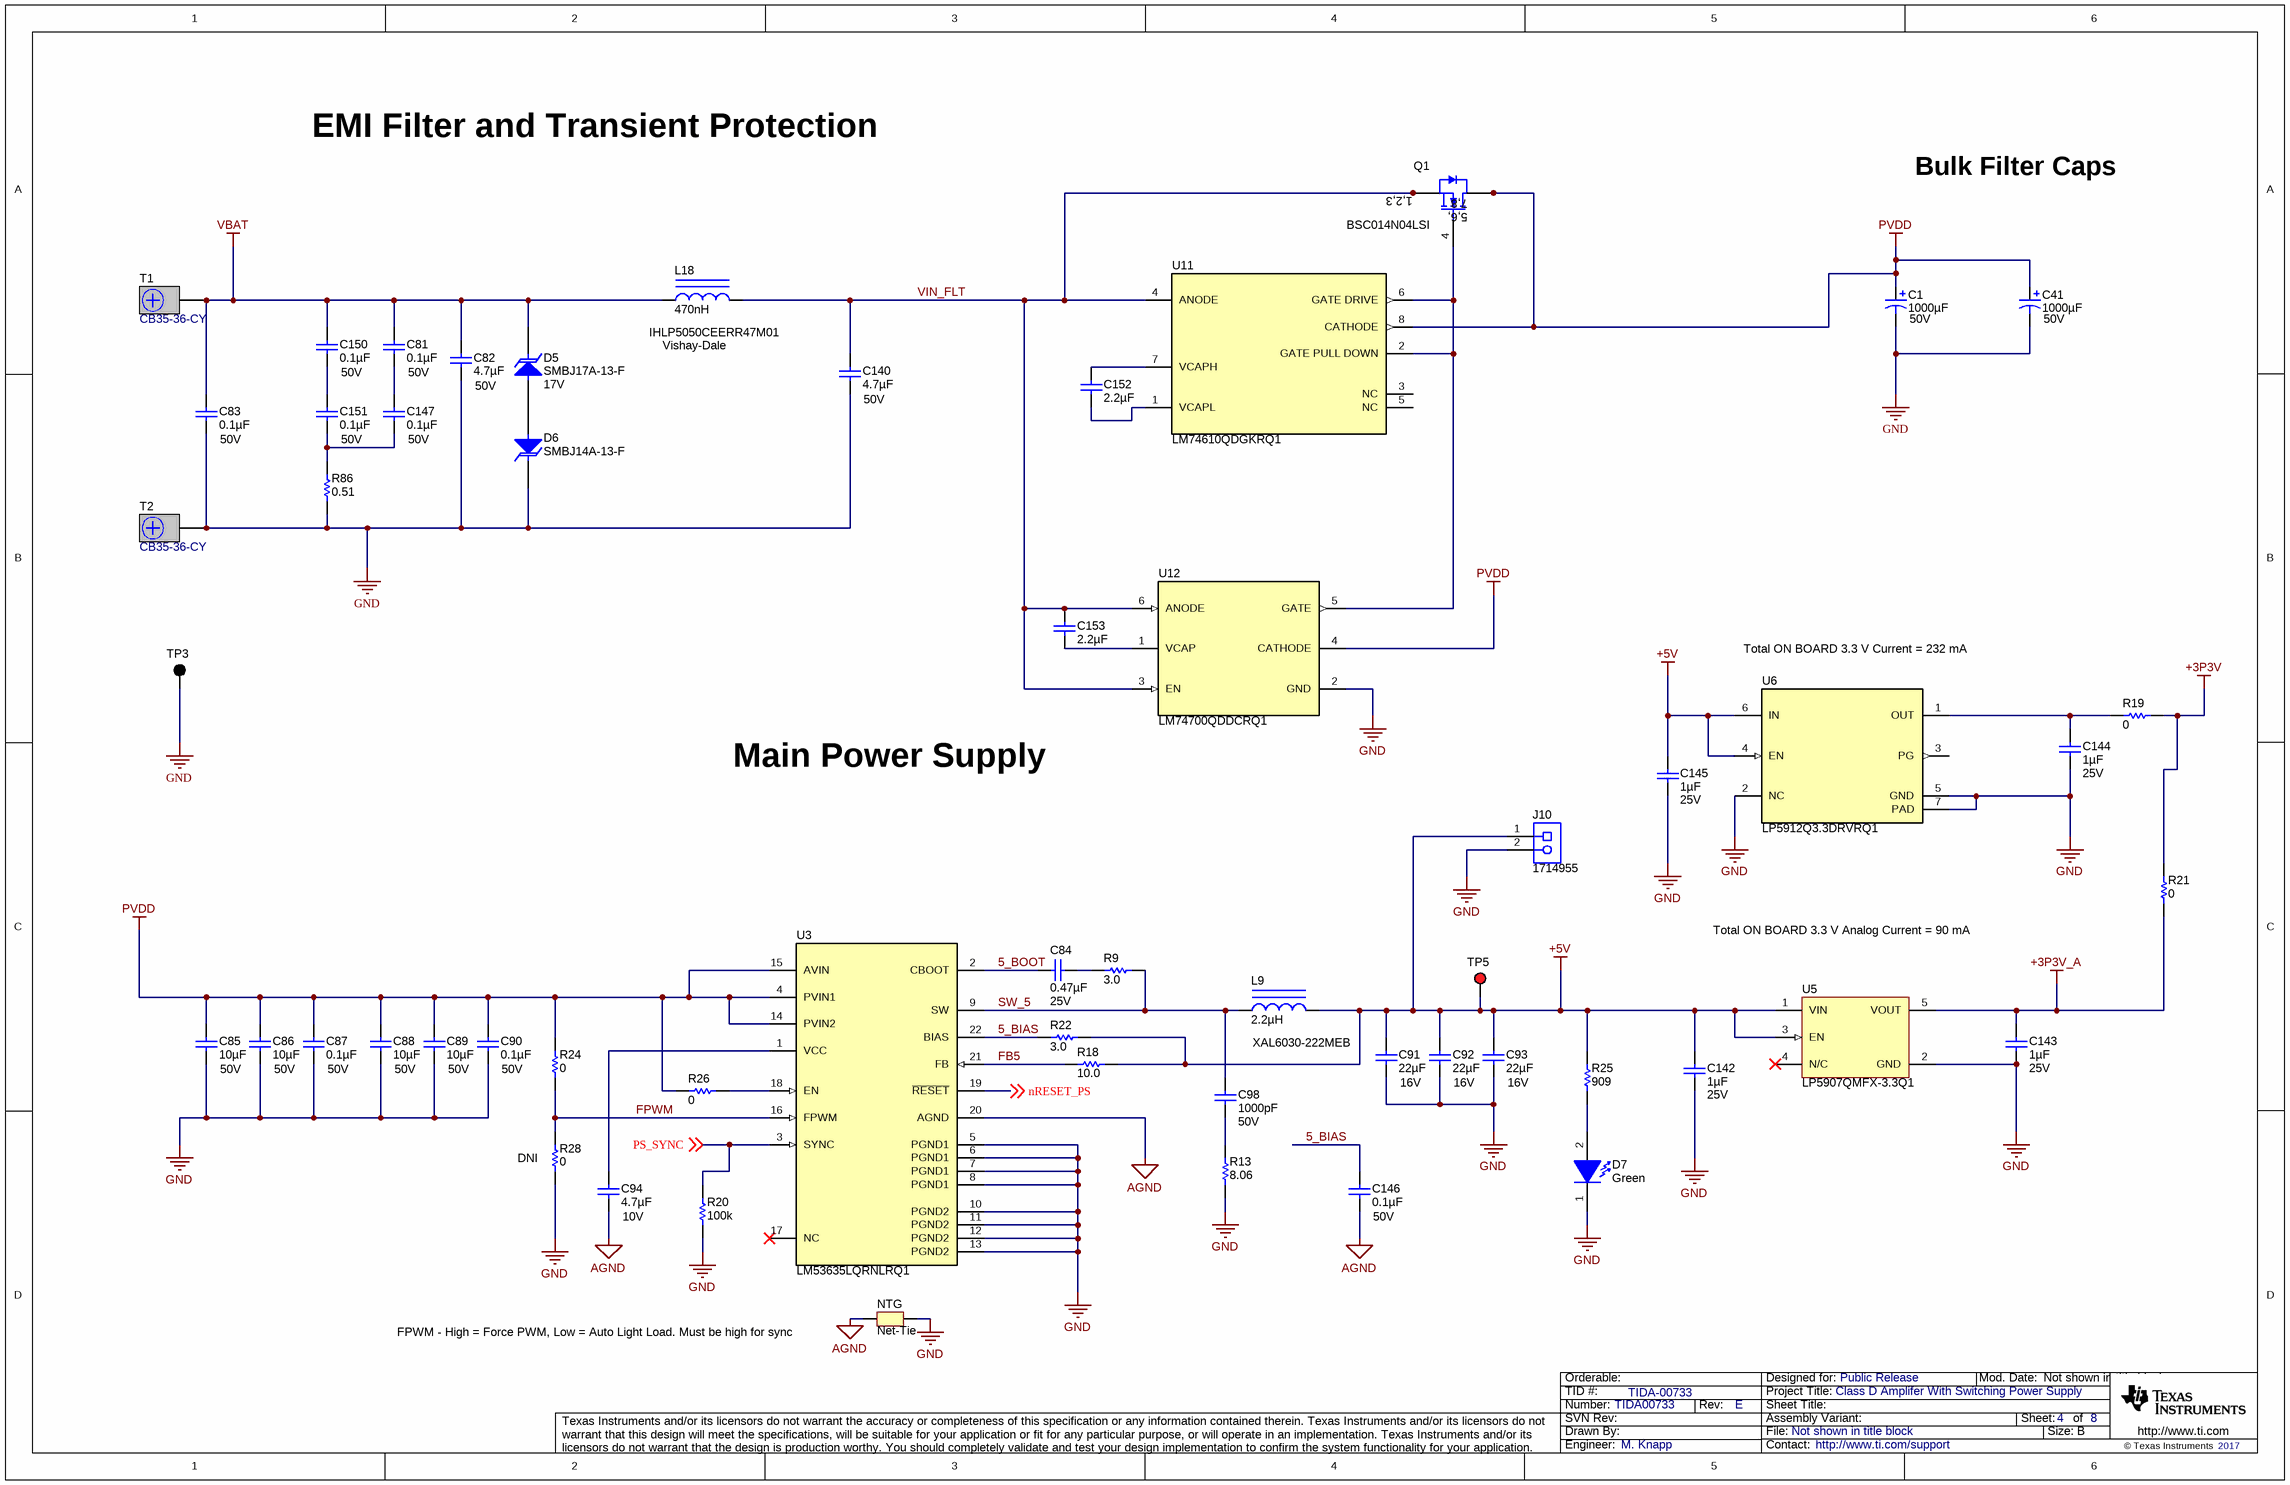
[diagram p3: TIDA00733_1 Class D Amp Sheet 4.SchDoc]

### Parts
C1  ValueDisplayed: 1000µF  Value2: 50V  [SM_RADIAL_J16]  (hidden comment: EEV-FK1H102M)
C41  ValueDisplayed: 1000µF  Value2: 50V  [SM_RADIAL_J16]  (hidden comment: EEV-FK1H102M)
C81  ValueDisplayed: 0.1µF  Value2: 50V  [0402L]  (hidden comment: C1005X7R1H104K050BB)
C82  ValueDisplayed: 4.7µF  Value2: 50V  [1206_180]  (hidden comment: GRM31CR71H475KA12L)
C83  ValueDisplayed: 0.1µF  Value2: 50V  [0402L]  (hidden comment: C1005X7R1H104K050BB)
C84  ValueDisplayed: 0.47µF  Value2: 25V  [0603L]  (hidden comment: GRM188R71E474KA12D)
C85  ValueDisplayed: 10µF  Value2: 50V  [1210_270]  (hidden comment: GRM32ER71H106KA12L)
C86  ValueDisplayed: 10µF  Value2: 50V  [1210_270]  (hidden comment: GRM32ER71H106KA12L)
C87  ValueDisplayed: 0.1µF  Value2: 50V  [0402L]  (hidden comment: C1005X7R1H104K050BB)
C88  ValueDisplayed: 10µF  Value2: 50V  [1210_270]  (hidden comment: GRM32ER71H106KA12L)
C89  ValueDisplayed: 10µF  Value2: 50V  [1210_270]  (hidden comment: GRM32ER71H106KA12L)
C90  ValueDisplayed: 0.1µF  Value2: 50V  [0402L]  (hidden comment: C1005X7R1H104K050BB)
C91  ValueDisplayed: 22µF  Value2: 16V  [1210_280]  (hidden comment: CGA6P1X7R1C226M250AC)
C92  ValueDisplayed: 22µF  Value2: 16V  [1210_280]  (hidden comment: CGA6P1X7R1C226M250AC)
C93  ValueDisplayed: 22µF  Value2: 16V  [1210_280]  (hidden comment: CGA6P1X7R1C226M250AC)
C94  ValueDisplayed: 4.7µF  Value2: 10V  [0805L]  (hidden comment: GRM21BR71A475KA73L)
C98  ValueDisplayed: 1000pF  Value2: 50V  [0603L]  (hidden comment: 06035A102KAT2A)
C140  ValueDisplayed: 4.7µF  Value2: 50V  [1206_180]  (hidden comment: GRM31CR71H475KA12L)
C142  ValueDisplayed: 1µF  Value2: 25V  [0603L]  (hidden comment: C1608X7R1E105K080AB)
C143  ValueDisplayed: 1µF  Value2: 25V  [0603L]  (hidden comment: C1608X7R1E105K080AB)
C144  ValueDisplayed: 1µF  Value2: 25V  [0603L]  (hidden comment: C1608X7R1E105K080AB)
C145  ValueDisplayed: 1µF  Value2: 25V  [0603L]  (hidden comment: C1608X7R1E105K080AB)
C146  ValueDisplayed: 0.1µF  Value2: 50V  [0402L]  (hidden comment: C1005X7R1H104K050BB)
C147  ValueDisplayed: 0.1µF  Value2: 50V  [0402L]  (hidden comment: C1005X7R1H104K050BB)
C150  ValueDisplayed: 0.1µF  Value2: 50V  [0402L]  (hidden comment: C1005X7R1H104K050BB)
C151  ValueDisplayed: 0.1µF  Value2: 50V  [0402L]  (hidden comment: C1005X7R1H104K050BB)
C152  ValueDisplayed: 2.2µF  [0805L]  (hidden comment: C2012X7R1H225K125AC)
C153  ValueDisplayed: 2.2µF  [0805L]  (hidden comment: C2012X7R1H225K125AC)
D5  SMBJ17A-13-F  value 17V  [SMB]
D6  SMBJ14A-13-F  [SMB]
D7  value Green  [WL-SMCW_GREEN]  (hidden comment: 150060VS75000)
J10  1714955  [Phoenix_1714955]
L9  ValueDisplayed: 2.2µH  [XAL6030]  (hidden comment: XAL6030-222MEB)
L18  ValueDisplayed: 470nH  Manufacturer: Vishay-Dale  [IHLP-5050CE]  (hidden comment: IHLP5050CEERR47M01)
NTG  Net-Tie  [Net-Tie_50milWide_30milLong]  (net tie, no BOM)
Q1  BSC014N04LSI  [TDSON-8_FL]
R9  ValueDisplayed: 3.0  [0402L]  (hidden comment: CRCW04023R00JNED)
R13  ValueDisplayed: 8.06  [0402L]  (hidden comment: CRCW04028R06FKED)
R18  ValueDisplayed: 10.0  [0402L]  (hidden comment: CRCW040210R0FKED)
R19  ValueDisplayed: 0  [0402L]  (hidden comment: CRCW04020000Z0ED)
R20  ValueDisplayed: 100k  [0402L]  (hidden comment: CRCW0402100KFKED)
R21  ValueDisplayed: 0  [0402L]  (hidden comment: CRCW04020000Z0ED)
R22  ValueDisplayed: 3.0  [0402L]  (hidden comment: CRCW04023R00JNED)
R24  ValueDisplayed: 0  [0402L]  (hidden comment: CRCW04020000Z0ED)
R25  ValueDisplayed: 909  [0402L]  (hidden comment: CRCW0402909RFKED)
R26  ValueDisplayed: 0  [0402L]  (hidden comment: CRCW04020000Z0ED)
R28  ValueDisplayed: 0  [0402L]  (hidden comment: CRCW04020000Z0ED)
R86  ValueDisplayed: 0.51  [0603]  (hidden comment: ERJ-3RQFR51V)
T1  CB35-36-CY  [CB35-36-CY]
T2  CB35-36-CY  [CB35-36-CY]
TP3  5011  [Keystone5011]  (value not drawn)
TP5  5010  [Keystone5010]  (value not drawn)
U3  LM53635LQRNLRQ1  [RNL0022A_NV]
U5  LP5907QMFX-3.3Q1  [DBV0005A_N]
U6  LP5912Q3.3DRVRQ1  [DRV0006A]
U11  LM74610QDGKRQ1  [DGK0008A_L]
U12  LM74700QDDCRQ1  [DDC0006A_N]

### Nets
+3P3V: R19.2 R21.2
+3P3V_A: C143.1 R21.1 U5.5(VOUT)
+5V: C91.1 C92.1 C93.1 C142.1 C145.1 J10.1 L9.2 R18.2 R22.2 R25.2 TP5.1 U5.1(VIN) U5.3(EN) U6.4(EN) U6.6(IN)
AGND: C94.2 C146.2 NTG.1 U3.20(AGND)
GND: C1.2(-) C41.2(-) C82.2 C83.2 C85.2 C86.2 C87.2 C88.2 C89.2 C90.2 C91.2 C92.2 C93.2 C140.2 C142.2 C143.2 C144.2 C145.2 D6.1(K) D7.1(K) J10.2 NTG.2 R13.1 R20.1 R28.2 R86.1 T2.1 TP3.1 U3.5(PGND1) U3.6(PGND1) U3.7(PGND1) U3.8(PGND1) U3.10(PGND2) U3.11(PGND2) U3.12(PGND2) U3.13(PGND2) U5.2(GND) U6.2(NC) U6.5(GND) U6.7(PAD) U12.2(GND)
PVDD: C1.1(+) C41.1(+) C85.1 C86.1 C87.1 C88.1 C89.1 C90.1 Q1.5(D) Q1.6(D) Q1.7(D) Q1.8(D) Q1.9(D) R24.1 R26.2 U3.4(PVIN1) U3.14(PVIN2) U3.15(AVIN) U11.8(CATHODE) U12.4(CATHODE)
VBAT: C81.1 C82.1 C83.1 C150.1 D5.1(K) L18.1 T1.1
5_BIAS: C146.1 R22.1 U3.22(BIAS)
5_BOOT: C84.2 U3.2(CBOOT)
FB5: R18.1 U3.21(FB)
FPWM: R24.2 R28.1 U3.16(FPWM)
nRESET_PS: U3.19(~{RESET}) ; off-sheet nRESET_PS
PS_SYNC: R20.2 U3.3(SYNC) ; off-sheet PS_SYNC
SW_5: C98.1 L9.1 R9.2 U3.9(SW)
VIN_FLT: C140.1 C153.1 L18.2 Q1.1(S) Q1.2(S) Q1.3(S) U11.4(ANODE) U12.3(EN) U12.6(ANODE)
NetC81_2: C81.2 C147.1
NetC84_1: C84.1 R9.1
NetC94_1: C94.1 U3.1(VCC)
NetC98_2: C98.2 R13.2
NetC144_1: C144.1 R19.1 U6.1(OUT)
NetC147_2: C147.2 C151.2 R86.2
NetC150_2: C150.2 C151.1
NetC152_1: C152.1 U11.7(VCAPH)
NetC152_2: C152.2 U11.1(VCAPL)
NetC153_2: C153.2 U12.1(VCAP)
NetD5_2: D5.2(A) D6.2(A)
NetD7_2: D7.2(A) R25.1
NetQ1_4: Q1.4(G) U11.2(GATE_PULL_DOWN) U11.6(GATE_DRIVE) U12.5(GATE)
NetR26_1: R26.1 U3.18(EN)

Not connected (* = marked no-connect by the designer): U3 17(NC)*; U5 4(N/C)*; U6 3(PG); U11 3(NC) 5(NC)

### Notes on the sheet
- EMI Filter and Transient Protection
- Bulk Filter Caps
- Total ON BOARD 3.3 V Current = 232 mA
- Main Power Supply
- Total ON BOARD 3.3 V Analog Current = 90 mA
- (near R28) DNI
- FPWM - High = Force PWM, Low = Auto Light Load. Must be high for sync

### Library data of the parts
C1 C41 = EEV-FK1H102M: CAP, AL, 1000 µF, 50 V, +/- 20%, 0.073 ohm, SMD; Manufacturer: Panasonic; Polarized: Y; CompType: Capacitor; Value: 1000uF; U/M: EA; Cap_F: 0.001; Tolerance_%: 20; VDC_V: 50; ESR_ohm: 0.073; IRMS_A: 1.61; TaMin_C: -55; TaMax_C: 105; Cap_Case: J16; AEC Category: Q200
C81 C83 C87 C90 C146 C147 C150 C151 = C1005X7R1H104K050BB: as C3 on sheet TIDA00733_1 Class D Amp Sheet 2
C82 C140 = GRM31CR71H475KA12L: CAP, CERM, 4.7 µF, 50 V, +/- 10%, X7R, 1206; Manufacturer: MuRata; Polarized: N; CompType: Capacitor; Value: 4.7uF; U/M: EA; Cap_F: 0.0000047; Tolerance_%: 10; Value1: Unknown; VDC_V: 50; TaMin_C: -55; TaMax_C: 125; Cap_Case: 2220; AEC Category: Q200; SizeArea_mm2: 5.12; SizeAreaWB_mm2: 10.92; SizeX_mm: 3.2; SizeY_mm: 1.6; SizeZ_mm: 1.8
C84 = GRM188R71E474KA12D: CAP, CERM, 0.47 µF, 25 V, +/- 10%, X7R, 0603; Manufacturer: MuRata; Polarized: N; CompType: Capacitor; Value: 0.47uF; U/M: EA; Cap_F: 0.00000047; Tolerance_%: 10; Value1: Unknown; VDC_V: 25; TaMin_C: -55; TaMax_C: 125; Cap_Case: 0603; AEC Category: Q200; SizeArea_mm2: 1.28; SizeAreaWB_mm2: 4.68; SizeX_mm: 1.6; SizeY_mm: 0.8; SizeZ_mm: 1
C85 C86 C88 C89 = GRM32ER71H106KA12L: as C2 on sheet TIDA00733_1 Class D Amp Sheet 2
C91-C93 = CGA6P1X7R1C226M250AC: CAP, CERM, 22 µF, 16 V, +/- 20%, X7R, AEC-Q200 Grade 1, 1210; Manufacturer: TDK; Polarized: N; CompType: Capacitor; Value: 22uF; U/M: EA; Cap_F: 0.000022; Tolerance_%: 20; ESR_ohm: 0.002582; Value1: 0.002582 ohm; VDC_V: 16; IRMS_A: 4.57562; TaMin_C: -55; TaMax_C: 125; AEC Category: Q200; AEC Qualified: Y; AEC Grade: 1; SizeArea_mm2: 8; SizeAreaWB_mm2: 14.7; SizeX_mm: 3.2; SizeY_mm: 2.5; SizeZ_mm: 2.8
C94 = GRM21BR71A475KA73L: CAP, CERM, 4.7 µF, 10 V, +/- 10%, X7R, 0805; Manufacturer: MuRata; Polarized: N; CompType: Capacitor; Value: 4.7uF; U/M: EA; Cap_F: 0.0000047; Tolerance_%: 10; Value1: Unknown; TaMin_C: -55; TaMax_C: 125; Cap_Case: 0805; SizeArea_mm2: 2.5; SizeAreaWB_mm2: 6.75; SizeX_mm: 2; SizeY_mm: 1.25; SizeZ_mm: 1.45; AEC Category: Q200
C98 = 06035A102KAT2A: CAP, CERM, 1000 pF, 50 V, +/- 10%, C0G/NP0, 0603; Manufacturer: AVX; Polarized: N; CompType: Capacitor; Value: 1000pF; U/M: EA; Cap_F: 0.000000001; Tolerance_%: 10; ESR_ohm: 0.048; Value1: 0.048 ohm; VDC_V: 50; TaMin_C: -55; TaMax_C: 125; Cap_Case: 0603; SizeArea_mm2: 1.28; SizeAreaWB_mm2: 4.68; SizeX_mm: 1.6; SizeY_mm: 0.8; SizeZ_mm: 1; AEC Category: Q200
C142-C145 = C1608X7R1E105K080AB: as C15 on sheet TIDA00733_1 Class D Amp Sheet 2
C152 C153 = C2012X7R1H225K125AC: as C14 on sheet TIDA00733_1 Class D Amp Sheet 2
D5 = SMBJ17A-13-F: Diode, TVS, Uni, 17 V, 600 W, SMB; Manufacturer: Diodes Inc.; U/M: EA; Power_W: 5; Vr_V: 17; Value1: 5W; AEC Category: Q101; SizeAreaWB_mm2: 44.156; SizeArea_mm2: 21.336; SizeX_mm: 5.6; SizeY_mm: 3.81; SizeZ_mm: 2.6
D6 = SMBJ14A-13-F: Diode, TVS, Uni, 14 V, 600 W, SMB; Manufacturer: Diodes Inc.; Value: 14V; U/M: EA; Power_W: 5; Vr_V: 14; Value1: 5W; AEC Category: Q101; SizeAreaWB_mm2: 44.156; SizeArea_mm2: 21.336; SizeX_mm: 5.6; SizeY_mm: 3.81; SizeZ_mm: 2.6
D7 = 150060VS75000: LED, Green, SMD; Manufacturer: Wurth Elektronik; Type: AlInGaP; Vf_V: 2; Value2: 2V; Io_A: 0.02; Value1: W; U/M: EA
J10 = 1714955: Terminal Block, 2x1, 6.35mm, Green, TH; Manufacturer: Phoenix Contact; SymbolCreator: a0412235; Pitch_mm: 6.35; Gender: Female; Shrouded: Y; Row_Count: 1
L9 = XAL6030-222MEB: Inductor, Shielded, Composite, 2.2 µH, 12.7 A, 0.012 ohm, SMD; Manufacturer: Coilcraft; Value: 2.2uH; Ind_H: 2.2E-6; Imax_A: 12.7; Irms: 12.7A @ 40C rise; Isat: 15.9A @ 30% inductance drop; DCR_ohm: 0.012; Value2: 12.7A; AEC Category: Q200
L18 = IHLP5050CEERR47M01: Inductor, Shielded Drum Core, Powdered Iron, 470 nH, 32 A, 0.0016 ohm, SMD; Value: 470nH; Ind_H: 470.0E-9; Imax_A: 32; Irms: 32A @ 40C rise; Isat: 55A @ 20% inductance drop; DCR_ohm: 0.0016; Value2: 32A; AEC Category: Q200; SizeAreaWB_mm2: 226.48; SizeArea_mm2: 170.28; SizeX_mm: 13.2; SizeY_mm: 12.9; SizeZ_mm: 3.5; Green_Lifecycle: Active; Green_REACh: Passed
NTG = Net-Tie: Single point connection between nets.; SymbolCreator: codlsc
Q1 = CMP-0000679-1: MOSFET, N-CH, 40 V, 100 A, 8-PowerTDFN; Alternate Manufacturer: None; Manufacturer: Infineon Technologies; SizeZ_mm: 1.1; ChType: N; Value2: 29 nC; Value1: 0; VdsMax_V: 40V; SizeX_mm: 6.15; SizeY_mm: 5.15; Vgs_V: 20V; Value: 40V; Rdson45_ohm: 2m; SizeArea_mm2: 31.6725; AEC Category: Q101; IdsMax_A: 100A; SizeAreaWB_mm2: 58.2725; U/M: EA; QgTyp_nC: 29
R9 R22 = CRCW04023R00JNED: RES, 3.0, 5%, 0.063 W, 0402; Manufacturer: Vishay-Dale; CompType: Resistor; Value: 3.0; Res_ohm: 3; Value_Code: 3R00; Tolerance_%: 5; Power_W: 0.063; Value2: 0.063W; VDC_V: 50; TempCo: 200 ppm/C; EIA_Code: E24; U/M: EA; AEC Category: Q200; SizeArea_mm2: 0.5; SizeX_mm: 1; SizeZ_mm: 0.6
R13 = CRCW04028R06FKED: RES, 8.06, 1%, 0.063 W, 0402; Manufacturer: Vishay-Dale; CompType: Resistor; Value: 8.06; Value_Code: 8R06; Tolerance_%: 1; Power_W: 0.063; Value2: 0.063W; VDC_V: 50; TempCo: 100 ppm/C; SizeArea_mm2: 0.5; SizeZ_mm: 0.6; EIA_Code: E96; U/M: EA; AEC Category: Q200
R18 = CRCW040210R0FKED: RES, 10.0, 1%, 0.063 W, 0402; Manufacturer: Vishay-Dale; CompType: Resistor; Value: 10.0; Res_ohm: 10; Value_Code: 10R0; Tolerance_%: 1; Power_W: 0.063; Value2: 0.063W; VDC_V: 50; TempCo: 100 ppm/C; SizeArea_mm2: 0.5; SizeZ_mm: 0.6; EIA_Code: E96; U/M: EA; AEC Category: Q200
R19 R21 R24 R26 R28 = CRCW04020000Z0ED: RES, 0, 5%, 0.063 W, 0402; Manufacturer: Vishay-Dale; CompType: Resistor; Value: 0; Value_Code: 0000; Tolerance_%: 5; Power_W: 0.063; Value2: 0.063W; VDC_V: 50; TempCo: 200 ppm/C; EIA_Code: E24; U/M: EA; AEC Category: Q200; SizeArea_mm2: 0.5; SizeX_mm: 1; SizeZ_mm: 0.6
R20 = CRCW0402100KFKED: RES, 100 k, 1%, 0.063 W, 0402; Manufacturer: Vishay-Dale; CompType: Resistor; Value: 100k; Res_ohm: 100000; Tolerance_%: 1; Power_W: 0.063; Value2: 0.063W; VDC_V: 50; TempCo: 100 ppm/C; SizeArea_mm2: 0.5; SizeZ_mm: 0.6; EIA_Code: E96; U/M: EA; AEC Category: Q200
R25 = CRCW0402909RFKED: RES, 909, 1%, 0.063 W, 0402; Manufacturer: Vishay-Dale; CompType: Resistor; Value: 909; Value_Code: 909R; Tolerance_%: 1; Power_W: 0.063; Value2: 0.063W; VDC_V: 50; TempCo: 100 ppm/C; EIA_Code: E96; U/M: EA; AEC Category: Q200; SizeArea_mm2: 0.5; SizeZ_mm: 0.6
R86 = ERJ-3RQFR51V: RES, 0.51, 1%, 0.1 W, AEC-Q200 Grade 1, 0603; Manufacturer: Panasonic; CompType: Resistor; Value: 0.51; Value_Code: R510; Tolerance_%: 1; Power_W: 0.1; Value2: 0.1W; TempCo: 300 ppm/C; SizeArea_mm2: 1.28; SizeX_mm: 1.6; SizeY_mm: 0.8; EIA_Code: E96; U/M: EA; AEC Category: Q200; AEC Qualified: Y; Green_Lifecycle: Active; Green_REACh: Passed
T1 T2 = CB35-36-CY: Terminal 50A Lug; Manufacturer: Panduit; SymbolCreator: crossc; CompType: Screw Terminal; ContactFinish: Copper; Voltage_V: 600; Cert_CULUS: Y
TP3 = 5011: Test Point, Multipurpose, Black, TH; Manufacturer: Keystone; CompType: Test Point Loop; ContactFinish: Silver
TP5 = 5010: Test Point, Multipurpose, Red, TH; Manufacturer: Keystone; CompType: Test Point Loop; ContactFinish: Silver
U3 = LM53635LQRNLRQ1: 2.5/3.5A Synchronous Buck Regulator for Automotive Applications, RNL0022A; Alternate PartNumber: LM53635LQRNLTQ1; Manufacturer: Texas Instruments; SymbolCreator: Altium; CompType: IC; U/M: EA; SizeArea_mm2: 20; SizeAreaWB_mm2: 42; SizeX_mm: 4; SizeY_mm: 5; SizeZ_mm: 0.9
U5 = LP5907QMFX-3.3Q1: Automotive 250-mA, Ultra-Low-Noise, Low-IQ LDO, DBV0005A (SOT-23-5); Manufacturer: Texas Instruments; SymbolCreator: a0799628; SizeArea_mm2: 8.12; SizeAreaWB_mm2: 14.82; SizeX_mm: 2.8; SizeY_mm: 2.9; SizeZ_mm: 1.45; CompType: IC; U/M: EA
U6 = LP5912Q3.3DRVRQ1: Ultra Low-Noise, 500-mA Linear Regulator for RF and Analog Circuits - Requires No Bypass Capacitor, DRV0006A; Alternate PartNumber: LP5912Q3.3DRVTQ1; Manufacturer: Texas Instruments; SymbolCreator: a0411947; SizeArea_mm2: 4; SizeAreaWB_mm2: 9; SizeX_mm: 2; SizeZ_mm: 0.8; CompType: IC; U/M: EA
U11 = CMP-0076397-1: Zero Iq Reverse Polarity Protection Smart Diode Controller, DGK0008A (VSSOP-8); Manufacturer: Texas Instruments; SizeAreaWB_mm2: 35.955; SizeArea_mm2: 15.655; SizeZ_mm: 1.1; Green_REACh: Passed; SizeY_mm: 3.1; Green_Lifecycle: Active; U/M: EA; CompType: IC; SizeX_mm: 5.05
U12 = CMP-0013281-3: Low Iq Always ON Smart Diode Controller, DDC0006A (SOT-6); Manufacturer: Texas Instruments; SizeZ_mm: 0.87; SizeX_mm: 1.65; SizeY_mm: 2.95; SizeArea_mm2: 4.8675; CompType: IC; U/M: EA; SizeAreaWB_mm2: 10.4675

## Sheet TIDA00733_1 Class D Amp Sheet 5.SchDoc
size 431 x 279 mm; Date: Not shown in title block; ApprovedBy: Not shown in title block; CheckedBy: Not shown in title block; Author: Not shown in title block; CompanyName: Not shown in title block; Engineer: Not shown in title block; Organization: Not shown in title block; Address1: Not shown in title block; Address2: Not shown in title block; Address3: Not shown in title block; Address4: Not shown in title block; DocumentNumber: 5; Revision: Use project parameter SCH_Rev; SheetNumber: 5; SheetTotal: 8; PageSetup: Record=PageOptions¦CenterHorizontal=True¦CenterVertical=True¦PrintScale=1.00¦XCorrection=1.00¦YCorrection=1.00¦PrintKind=0¦BorderSize=5000000¦LeftOffset=0¦BottomOffset=0¦Orientation=2¦PaperLength=1000¦PaperWidth=1000¦Scale=100¦PaperSource=15¦PrintQuality=600¦MediaType=1¦DitherType=10¦PaperKind=Letter¦PrintScaleMode=1
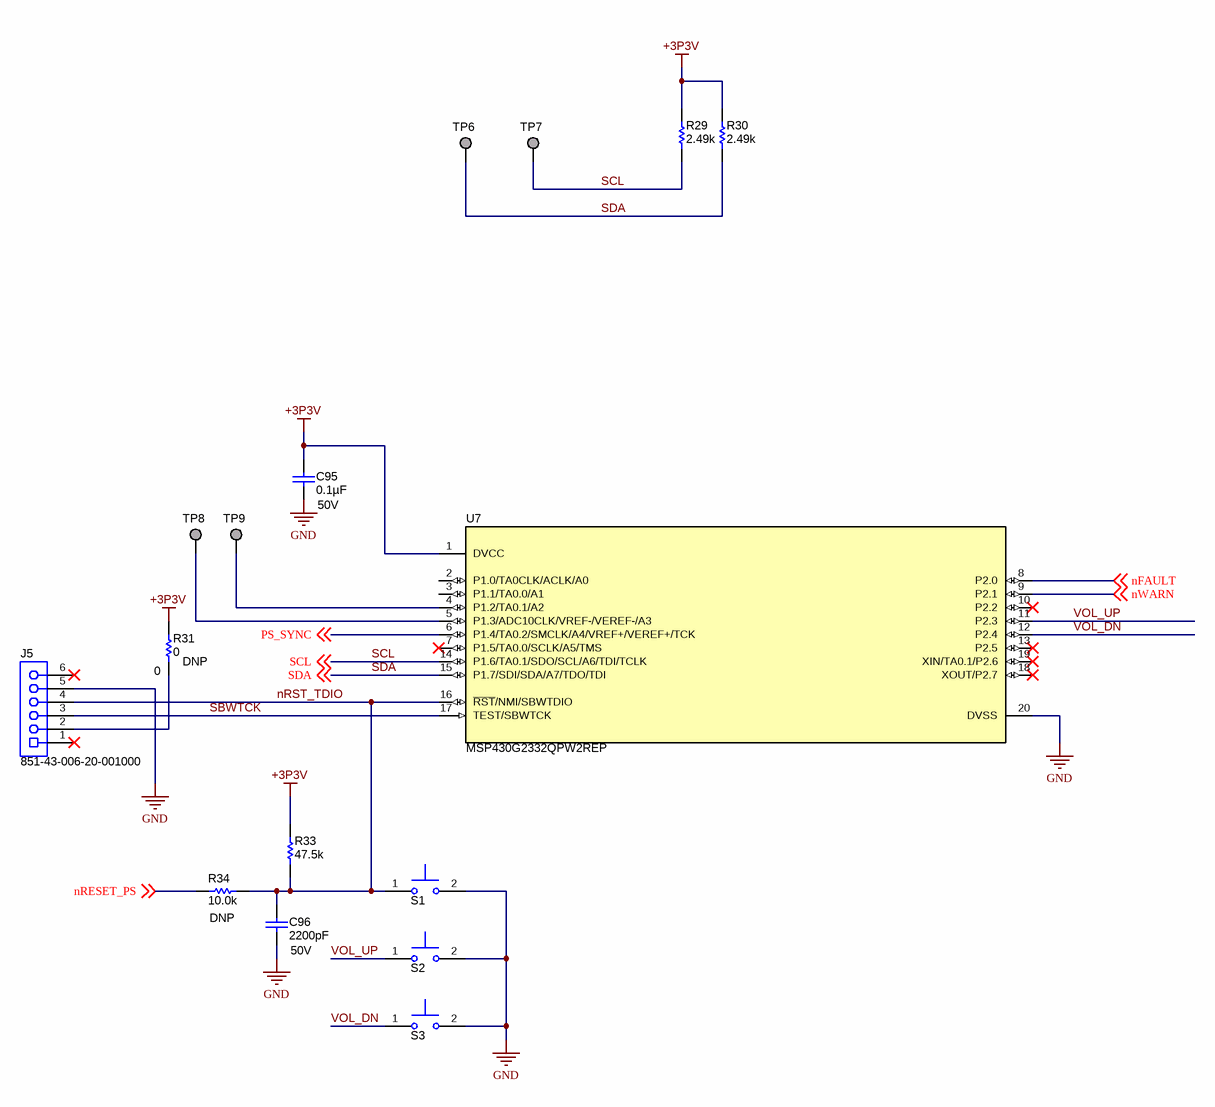
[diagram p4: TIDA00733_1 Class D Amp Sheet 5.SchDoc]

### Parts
C95  ValueDisplayed: 0.1µF  Value2: 50V  [0402L]  (hidden comment: C1005X7R1H104K050BB)
C96  ValueDisplayed: 2200pF  Value2: 50V  [0402L]  (hidden comment: GRM155R71H222KA01D)
J5  851-43-006-20-001000  [CONN_851-43-006-20-001000]
R29  ValueDisplayed: 2.49k  [0402L]  (hidden comment: CRCW04022K49FKED)
R30  ValueDisplayed: 2.49k  [0402L]  (hidden comment: CRCW04022K49FKED)
R31  value 0  [0603L]  (hidden comment: CRCW06030000Z0EA)
R33  ValueDisplayed: 47.5k  [0402L]  (hidden comment: CRCW040247K5FKED)
R34  ValueDisplayed: 10.0k  [0402L]  (hidden comment: CRCW040210K0FKED)
S1  SKRKAEE010  [SW_SKRKAEE010]  (value not drawn)
S2  SKRKAEE010  [SW_SKRKAEE010]  (value not drawn)
S3  SKRKAEE010  [SW_SKRKAEE010]  (value not drawn)
TP6  TESTPOINT  [PAD_1MM_SQUARE]  (value not drawn)  (no BOM)
TP7  TESTPOINT  [PAD_1MM_SQUARE]  (value not drawn)  (no BOM)
TP8  TESTPOINT  [PAD_1MM_SQUARE]  (value not drawn)  (no BOM)
TP9  TESTPOINT  [PAD_1MM_SQUARE]  (value not drawn)  (no BOM)
U7  MSP430G2332QPW2REP  [PW0020A_N]

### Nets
+3P3V: C95.1 R29.2 R30.2 R31.2 R33.2 U7.1(DVCC)
GND: C95.2 C96.2 J5.5 S1.2 S2.2 S3.2 U7.20(DVSS)
nFAULT: U7.8(P2.0) ; off-sheet nFAULT
nRESET_PS: R34.1 ; off-sheet nRESET_PS
nRST_TDIO: C96.1 J5.4 R33.1 R34.2 S1.1 U7.16(~{RST}/NMI/SBWTDIO)
nWARN: U7.9(P2.1) ; off-sheet nWARN
PS_SYNC: U7.6(P1.4/TA0.2/SMCLK/A4/VREF+/VEREF+/TCK) ; off-sheet PS_SYNC
SBWTCK: J5.3 U7.17(TEST/SBWTCK)
SCL: R29.1 TP7.1 U7.14(P1.6/TA0.1/SDO/SCL/A6/TDI/TCLK) ; off-sheet SCL
SDA: R30.1 TP6.1 U7.15(P1.7/SDI/SDA/A7/TDO/TDI) ; off-sheet SDA
VOL_DN: S3.1 U7.12(P2.4)
VOL_UP: S2.1 U7.11(P2.3)
NetJ5_2: J5.2 R31.1
NetTP8_1: TP8.1 U7.5(P1.3/ADC10CLK/VREF-/VEREF-/A3)
NetTP9_1: TP9.1 U7.4(P1.2/TA0.1/A2)

Not connected (* = marked no-connect by the designer): J5 1* 6*; U7 2(P1.0/TA0CLK/ACLK/A0) 3(P1.1/TA0.0/A1) 7(P1.5/TA0.0/SCLK/A5/TMS)* 10(P2.2)* 13(P2.5)* 18(XOUT/P2.7)* 19(XIN/TA0.1/P2.6)*

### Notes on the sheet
- (near R31) DNP
- (near R34) DNP

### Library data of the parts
C95 = C1005X7R1H104K050BB: as C3 on sheet TIDA00733_1 Class D Amp Sheet 2
C96 = GRM155R71H222KA01D: CAP, CERM, 2200 pF, 50 V, +/- 10%, X7R, 0402; Manufacturer: MuRata; Polarized: N; CompType: Capacitor; Value: 2200pF; U/M: EA; Cap_F: 0.0000000022; Tolerance_%: 10; Value1: Unknown; VDC_V: 50; TaMin_C: -55; TaMax_C: 125; Cap_Case: 0402; SizeArea_mm2: 0.5; SizeAreaWB_mm2: 3; SizeX_mm: 1; SizeZ_mm: 0.6; AEC Category: Q200
J5 = 851-43-006-20-001000: Receptacle, 50mil, 6x1, Gold, R/A, TH; Manufacturer: Mill-Max; SymbolCreator: a0411947
R29 R30 = CRCW04022K49FKED: RES, 2.49 k, 1%, 0.063 W, 0402; Manufacturer: Vishay-Dale; CompType: Resistor; Value: 2.49k; Res_ohm: 2490; Value_Code: 2k49; Tolerance_%: 1; Power_W: 0.063; Value2: 0.063W; VDC_V: 50; TempCo: 100 ppm/C; EIA_Code: E96; U/M: EA; AEC Category: Q200; SizeArea_mm2: 0.5; SizeZ_mm: 0.6
R31 = CRCW06030000Z0EA: RES, 0, 5%, 0.1 W, 0603; Manufacturer: Vishay-Dale; CompType: Resistor; Value_Code: 0000; Tolerance_%: 5; Power_W: 0.1; Value2: 0.1W; VDC_V: 75; TempCo: 200 ppm/C; EIA_Code: E24; U/M: EA; AEC Category: Q200; SizeArea_mm2: 1.28; SizeX_mm: 1.6; SizeY_mm: 0.8; SizeZ_mm: 1
R33 = CRCW040247K5FKED: RES, 47.5 k, 1%, 0.063 W, 0402; Manufacturer: Vishay-Dale; CompType: Resistor; Value: 47.5k; Res_ohm: 47500; Value_Code: 47k5; Tolerance_%: 1; Power_W: 0.063; Value2: 0.063W; VDC_V: 50; TempCo: 100 ppm/C; EIA_Code: E96; U/M: EA; AEC Category: Q200; SizeArea_mm2: 0.5; SizeZ_mm: 0.6
R34 = CRCW040210K0FKED: as R5 on sheet TIDA00733_1 Class D Amp Sheet 2
S1-S3 = SKRKAEE010: Switch, Push Button, SMD; Manufacturer: Alps; SymbolCreator: a0412235; Circuit: SPST-NO; VDC_V: 12; SwitchFunction: Off-Mom; PositionCount: 1; CurrentRating_mA: 50
TP6-TP9 = PAD_1MM_SQUARE: 1.0x1.0mm pad, square, SMD; Manufacturer: Any
U7 = MSP430G2332QPW2REP: MIXED SIGNAL MICROCONTROLLER, PW0020A; Alternate PartNumber: MSP430G2332QPW2EP; Manufacturer: Texas Instruments; SymbolCreator: Altium; CompType: IC; U/M: EA; SizeArea_mm2: 43.56; SizeAreaWB_mm2: 73.96; SizeX_mm: 6.6; SizeZ_mm: 1.2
